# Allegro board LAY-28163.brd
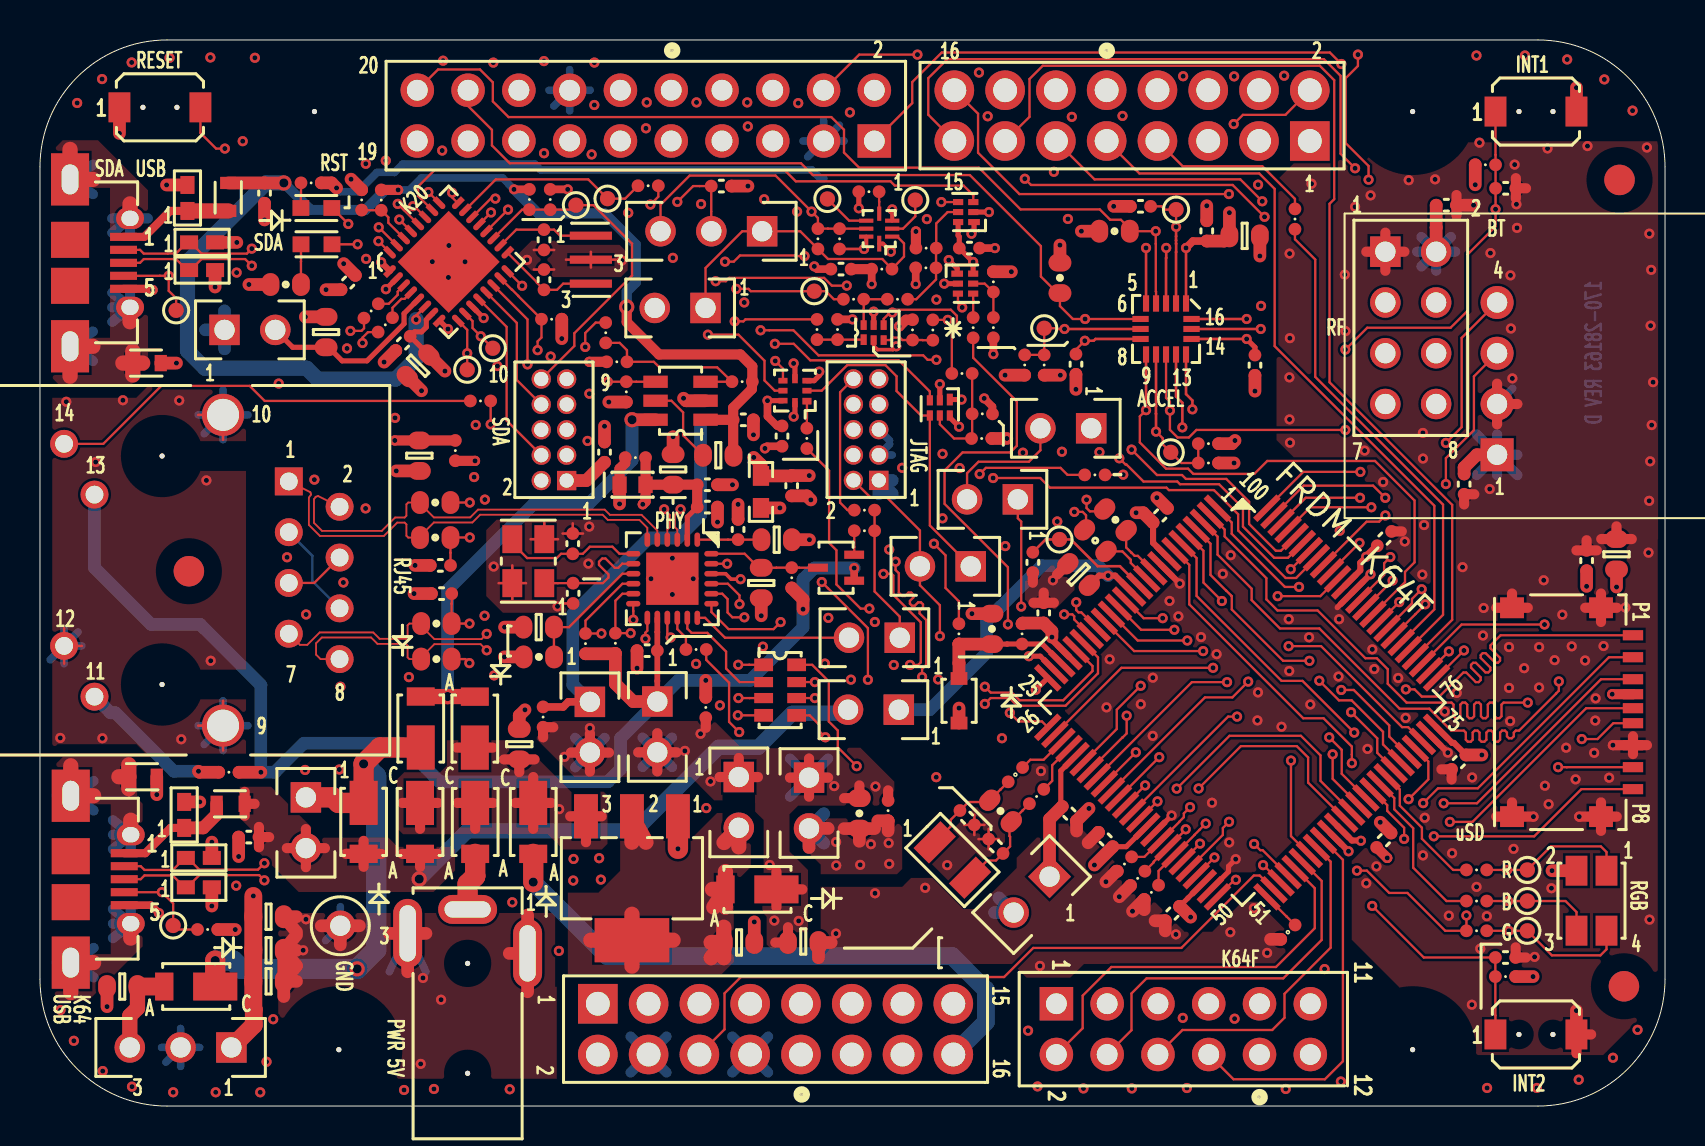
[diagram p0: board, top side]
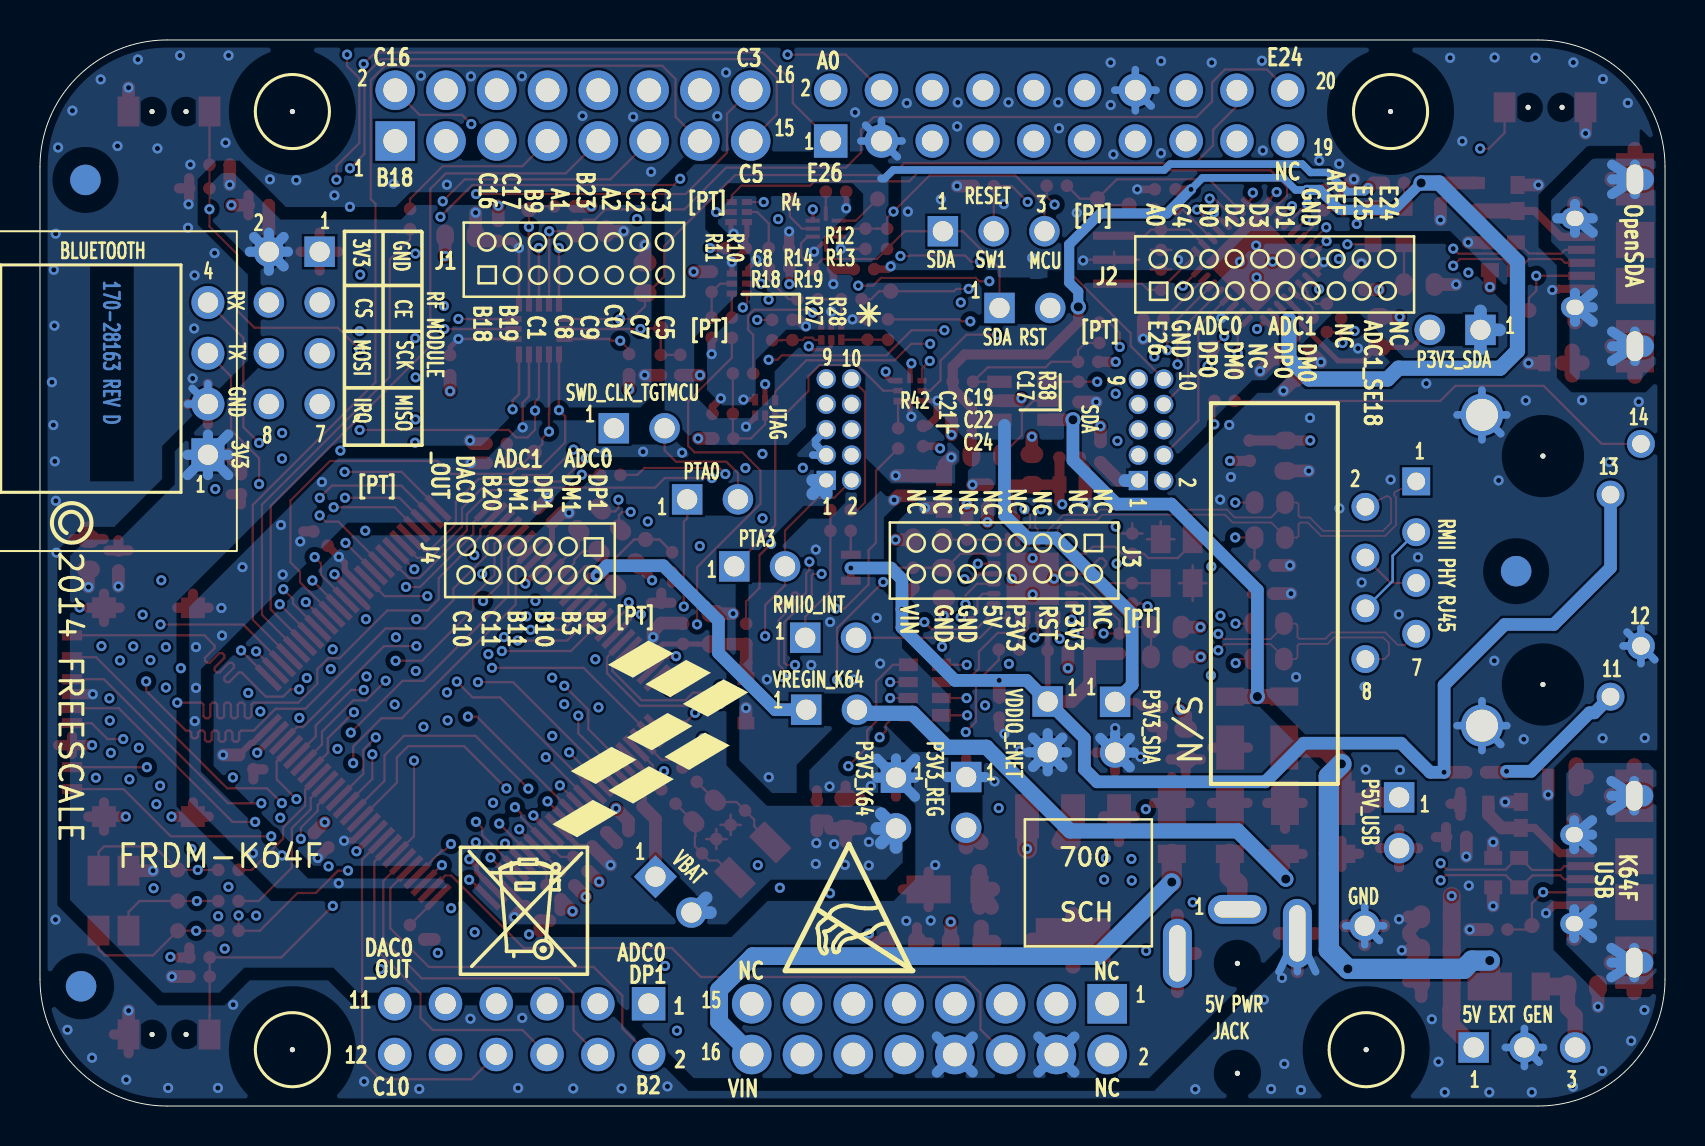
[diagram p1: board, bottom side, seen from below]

Outline 81.28 x 53.34 mm; copper layers: TOP, GND, INT_1, BOTTOM. Coordinates in mm from the lower left corner of the outline.
Outline path: 0,46.99 arc(1.86,51.48) 6.35,53.34 74.93,53.34 arc(79.42,51.48) 81.28,46.99 81.28,6.35 arc(79.42,1.86) 74.93,0 6.35,0 arc(1.86,1.86) 0,6.35 0,46.99

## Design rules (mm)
net group ADC0: nets ADC0_DM0/ADC1_DM3 ADC0_DP0/AD1_DP3
net group ADC1: nets ADC1_DM0/ADC0_DM3 ADC1_DP0/ADC0_DP3
net group ENET1_RX: nets ENET1_RX+ ENET1_RX-
net group ENET1_TX: nets ENET1_TX+ ENET1_TX-
net group LEDRGB_BLUE: nets LEDRGB_BLUE PTB21
net group LEDRGB_GREEN: nets LEDRGB_GREEN PTE26
net group LEDRGB_RED: nets LEDRGB_RED PTB22
net group PTB16: nets PTB16 UART1_RX_TGTMCU_BUF
net group PTB17: nets PTB17 UART1_TX_TGTMCU_BUF
net group RMII_RXCLK: nets RMII_RXCLK RXCLK
net group SDA_SWD_EN_B_R: nets SDA_SWD_EN_B SDA_SWD_EN_B_R
net group SDA_SWD_OE_B_R: nets SDA_SWD_OE_B SDA_SWD_OE_B_R
net group TRACE_SWO: nets PTA2 TRACE_SWO
net group USB_CONN_DN: nets K64_MICRO_USB_DN USB_CONN_DN
net group USB_CONN_DP: nets K64_MICRO_USB_DP USB_CONN_DP
net group USB_SI_CONN_D: nets SDA_USB_CONN_DN SDA_USB_CONN_DP
net group VTRG_EN: nets POWER_EN VTRG_EN
net group ANALOG: nets ADC0_DM1 ADC0_DP1 ADC1_DM1 ADC1_DP1 ADC1_SE18 DAC0_OUT PTB2 PTB3 PTB10 PTB11 PTC11
net group CLOCKS: nets PTB18 PTC3 PTC6 PTC8 PTD1 PTE0 RMII_XTALI RMII_XTALO SDA_EXTAL SWD_CLK_TGTMCU SWD_CLK_TGTMCU_BUF XTAL_K64_MAIN
net group CPU_PER_1_RST_B: nets CPU_PER_1_RST_B PHY_RST_B RST_TGTMCU_B SDA_RST_LED SDA_RST_TGTMCU_J_B V_TGTMCU
net group EXTAL32_RTC: nets EXTAL32_RTC EXTAL_32.768KHZ XTAL32_RTC XTAL_32.768KHZ
net group POW: nets VREFH
net group POWER_SPACE: nets P5-9V_VIN P5V0_SDA_USB_CONN_VBUS P5V0_USB_CONN_VBUS P5V_SDA P5V_USB SDA_VOUT33 VBAT VDDA_ENET VOUT33_K64 VREGIN_K64
net group SDA_SWD_EN_R: nets SDA_SPI0_RST_B SDA_SWD_EN SDA_SWD_EN_R
net group SDA_SWD_OE_R: nets SDA_SPI0_CS SDA_SWD_OE SDA_SWD_OE_R
net group SDA_USB_CONN_DP: nets SDA_USB_DP
net group USB_SI_D: nets SDA_USB_DN
nets with their own width: min track width 0.127; nets GND

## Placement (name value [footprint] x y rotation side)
C1  1.0UF  [CC0402_25]  11.23 45.68 270 top
C2  1000pF  [CC0402_25]  34.08 46.03 0 top
C3  0.1UF  [CC0402_25]  55.04 45.02 180 top
C4  0.1UF  [CC0402_25]  58.36 43.79 90 top
C5  4.7uF  [CC0603_OV]  60.25 43.54 0 top
C6  22PF  [CC0402_25]  25.21 43.34 270 top
C7  0.1UF  [CC0402_25]  46.49 42.93 0 top
C8  0.1UF  [CC0402_25]  40.07 41.87 180 top
C9  22PF  [CC0402_25]  25.21 41.35 90 top
C10  0.1UF  [CC0402_25]  15.42 41.2 225 top
C11  2.2UF  [CC0603_OV]  14.31 38.72 90 top
C12  1.0UF  [CC0402_25]  18.16 38.16 225 top
C13  0.1UF  [CC0402_25]  51.82 37.12 270 top
C14  0.1UF  [CC0402_25]  60.77 37.07 270 top
C15  10uF  [CC0603_OV]  18.91 37.04 225 top
C16  0.1UF  [CC0402_25]  35.18 34.33 0 top
C17  4.7uF  [CC0402_25]  37.11 33.52 270 top
C18  0.1UF  [CC0402_25]  28.24 32.72 90 top
C19  18PF  [CC0603_OV]  33.93 32.56 180 top
C20  10UF  [CC0603_OV]  18.97 32.54 270 top
C21  4.7UF  [CC0603_OV]  31.67 31.85 90 top
C22  0.1UF  [CC0402_25]  33.38 31.08 0 top
C23  4.7uF  [CC0402_25]  37.6 31.04 270 top
C24  0.1UF  [CC0402_25]  33.38 29.97 0 top
C25  0.1UF  [CC0402_25]  56.03 29.55 45 top
C26  0.1UF  [CC0402_25]  34.92 28.85 90 top
C27  0.1UF  [CC0402_25]  67.25 28.39 45 top
C28  1.0 UF  [CC0603_OV]  36.85 28.34 0 top
C29  24PF  [CC0402_25]  26.65 28.14 90 top
C30  10uF  [CC0603_OV]  78.85 27.61 90 top
C31  0.1UF  [CC0402_25]  20.03 27.05 180 top
C32  0.1UF  [CC0402_25]  77.36 27.29 90 top
C33  10uF  [CC0603_OV]  51.95 26.59 135 top
C34  10UF  [CC0603_OV]  36.08 26.17 270 top
C35  24PF  [CC0402_25]  26.66 25.65 270 top
C36  0.1UF  [CC0402_25]  20.09 25.64 180 top
C37  0.1UF  [CC0402_25]  50.2 24.67 90 top
C38  100PF  [CC0603_OV]  24.95 23.96 180 top
C39  0.1UF  [CC0402_25]  30.37 22.78 180 top
C40  2.2UF  [CC0603_OV]  38.18 8.18 0 top
C41  10uF  [CC0603_OV]  23.97 18.11 90 top
C42  0.1UF  [CC0402_25]  70.97 17.21 225 top
C43  0.1UF  [CC0402_25]  51.49 14.63 315 top
C44  12PF  [CC0402_25]  46.37 14.43 315 top
C45  1.0UF  [CC0402_25]  10.44 13.46 180 top
C46  0.1UF  [CC0402_25]  53.3 13.33 135 top
C47  0.1UF  [CC0402_25]  67.22 13.3 45 top
C48  12PF  [CC0402_25]  47.81 13 135 top
C49  0.1UF  [CC0402_25]  56.64 9.63 225 top
C50  10uF  [CC0603_OV]  11.43 9.47 0 top
C51  10uF  [CC0603_OV]  34.97 8.18 0 top
C52  10uF  [CC0603_OV]  11.43 7.79 0 top
C53  10uF  [CC0603_OV]  4.11 5.98 180 top
C54  10uF  [CC0603_OV]  11.43 6.24 0 top
C55  0.1UF  [CC0402_25]  73.3 7.43 0 top
C56  0.1UF  [CC0402_25]  73.31 45.92 0 top
C57  0.1UF  [CC0402_25]  70.34 45.07 0 top
C58  0.1UF  [CC0402_25]  71.23 31.12 270 top
C59  2.2uF  [CC0402_25]  49.66 27.2 270 top
D1  RED  [LED_0603]  13.82 44.93 0 top
D2  LED GREEN  [LED_0603]  13.83 43.12 0 top
D3  BAT54AWT1G  [SOT323_3P]  39.82 26.93 90 top
D4  3.0V  [SOD-323-A]  45.97 20.28 270 top
D5  DFLS130L-7  [POWERDI-123_3MMX2MM]  19.04 18.79 90 top
D6  DFLS130L-7  [POWERDI-123_3MMX2MM]  21.75 18.78 90 top
D7  DFLS130L-7  [POWERDI-123_3MMX2MM]  16.19 14.32 270 top
D8  DFLS130L-7  [POWERDI-123_3MMX2MM]  19.01 14.32 270 top
D9  DFLS130L-7  [POWERDI-123_3MMX2MM]  21.77 14.32 270 top
D10  DFLS130L-7  [POWERDI-123_3MMX2MM]  24.67 14.32 270 top
D11  DFLS130L-7  [POWERDI-123_3MMX2MM]  35.98 10.84 180 top
D12  CLV1A-FKB-CJ1M1F1BB7R4S3  [LED4_3P4X3MM_SMT]  77.6 10.27 0 top
D13  DFLS130L-7  [POWERDI-123_3MMX2MM]  7.91 5.98 180 top
J1  SSW-108-01-T-D  [CON_SKT2X8_TH]  63.51 48.29 0 top
J2  CON_2X10  [CON2X10_2P54_TH]  41.73 48.29 270 top
J3  SSW-108-01-T-D  [CON_SKT2X8_TH]  27.9 5.12 180 top
J4  SKT_2X6  [CON_SKT2X6_TH]  50.84 5.12 180 top
J5  HDR 1X2 TH  [SH_HDR102_BOTTOM]  33.29 39.93 270 top
J6  HDR_2X4  [HDR2X4]  67.29 42.75 0 top
J7  HDR 1X2 TH  [SH_HDR102_BOTTOM]  9.23 38.83 90 top
J8  HDR 1X2 TH  [SH_HDR102_BOTTOM]  52.58 33.91 270 top
J9  HDR 2X5  [HDR_5X2_FTSH_TH_NSP]  41.96 31.3 180 top
J10  HDR 2X5  [HDR_5X2_FTSH_TH_NSP]  26.34 31.3 180 top
J11  HDR 1X2 TH  [SH_HDR102_BOTTOM]  48.91 30.36 270 top
J12  HDR 1X2 TH  [SH_HDR102_BOTTOM]  46.55 27 270 top
J13  RB1-125BAG1A  [CON_RJ45_8P_2P54_TH_RA]  12.45 31.25 90 top
J14  HDR 1X2  [HDR102]  43 23.43 270 top
J15  CON microSD  [CON8_SDCARD_PUSH_SM]  75.75 19.71 90 top
J16  HDR 1X2 TH  [SH_HDR102_BOTTOM]  42.96 19.83 270 top
J17  HDR 1X2  [HDR102]  30.88 20.24 0 top
J18  HDR 1X2  [HDR102]  27.51 20.22 0 top
J19  HDR 1X2 TH  [SH_HDR102_BOTTOM]  34.95 16.46 0 top
J20  HDR 1X2  [HDR102]  38.47 16.43 0 top
J21  HDR 1X2  [HDR102]  13.3 15.44 0 top
J22  MICRO USB AB 5  [CON5_MICROUSB]  1.54 11.35 270 top
J23  HDR 1X2 TH  [SH_HDR102_BOTTOM]  50.5 11.48 315 top
J24  CON PWR 3  [CON_JACK_PJ1_022_TH-RA]  21.39 9.84 90 top
J25  HDR_1X3  [HDR103]  36.12 43.77 270 top
J26  MICRO USB AB 5  [CON5_MICROUSB]  1.5 42.19 270 top
J27  HDR_1X3  [HDR103]  9.57 2.93 270 top
J199  CON_1X4  [CON1X4_100_TH_RA]  72.88 32.59 90 bottom
L1  330 OHM  [IND_1608]  9.42 45.49 90 top
L2  330 OHM  [IND_1608]  5.34 37.17 0 top
L3  120OHM  [0603_CC]  29.64 31.09 0 top
L4  330 OHM  [IND_1608]  5.14 16.47 0 top
L5  330 OHM  [IND_1608]  9.54 15.12 0 top
NOREF  -  []  -381.97 185.27 0 top
NOREF#2  -  []  57.81 43.38 0 top
NOREF#3  -  []  42.18 43.28 90 top
NOREF#4  -  []  55.32 37.6 0 top
NOREF#5  -  []  6.11 21.09 90 top
NOREF#6  -  []  55.32 37.6 90 top
NOREF#7  -  [unnamed#2]  7.45 26.76 0 top
NOREF#8  -  []  70.32 0.01 90 top
NOREF#9  -  []  -239.61 -215.75 0 top
NOREF#10  -  []  24.14 10.61 0 top
NOREF#11  -  []  12.45 31.25 90 top
NOREF#12  -  []  55.05 39.38 90 top
NOREF#13  -  []  0 41.47 0 top
NOREF#14  -  []  12.45 31.25 90 top
NOREF#15  -  []  12.45 23.63 0 top
NOREF#16  -  []  1.21 23.02 90 top
NOREF#17  -  []  57.82 40.38 90 top
NOREF#18  -  []  13.74 2.72 0 top
NOREF#19  -  []  35.45 17.74 90 top
NOREF#20  -  []  55.32 37.6 0 top
NOREF#21  -  []  12.88 1.39 0 top
NOREF#22  -  []  12.45 31.25 0 top
NOREF#23  -  []  6.11 32.52 90 top
NOREF#24  -  []  55.32 37.6 0 top
NOREF#25  -  []  42.6 44.62 270 top
NOREF#26  -  []  2.73 30.59 90 top
NOREF#27  -  []  42.63 43.9 270 top
NOREF#28  -  []  79.64 51.25 0 top
NOREF#29  -  []  12.45 31.25 90 top
NOREF#30  -  []  192.91 64.47 0 top
NOREF#31  -  []  42.63 44.3 90 top
NOREF#32  -  []  -408 -339.88 0 top
NOREF#33  -  []  1.21 23.02 0 top
NOREF#34  -  []  65.9 33.73 0 top
NOREF#35  -  [unnamed#2]  79.23 5.99 0 top
NOREF#36  -  []  55.05 38.88 90 top
NOREF#37  -  []  54.82 40.38 0 top
NOREF#38  -  []  14.99 29.98 90 top
NOREF#39  -  []  -115.86 -175.27 0 top
NOREF#40  -  []  17.32 17.74 0 top
NOREF#41  -  []  65.9 33.73 90 top
NOREF#42  -  []  13.74 2.72 0 top
NOREF#43  -  []  55.05 38.38 0 top
NOREF#44  -  [unnamed#2]  79 46.34 0 top
NOREF#45  -  []  9.16 19.03 90 top
NOREF#46  -  []  -16.59 -36.7 0 top
NOREF#47  -  []  79.75 41.86 180 top
NOREF#48  -  [unnamed#2]  7.45 26.76 180 bottom
NOREF#49  -  [unnamed#2]  79.23 5.99 180 bottom
NOREF#50  -  []  120.45 -123.7 180 bottom
NOREF#51  -  []  54.61 5.51 180 bottom
NOREF#52  -  []  74.41 -23.78 0 bottom
NOREF#53  -  [unnamed#2]  68.66 2.82 180 bottom
NOREF#54  -  []  70.12 -27.59 180 bottom
NOREF#55  -  []  51.23 -43.91 270 bottom
NOREF#56  -  [unnamed#2]  13.73 49.76 180 bottom
NOREF#57  -  [unnamed#2]  14.95 2.82 180 bottom
NOREF#58  -  []  54.66 12.88 180 bottom
NOREF#59  -  []  20.69 32.09 270 bottom
NOREF#60  -  []  59.2 8.4 180 bottom
NOREF#61  -  [unnamed#2]  79.01 46.34 180 bottom
NOREF#62  -  [unnamed#2]  68.66 49.76 180 bottom
NOREF#63  -  []  55.65 13.45 180 bottom
NOREF#64  -  []  91.82 39.52 180 bottom
R1  10.0K  [RC0402_25]  72.3 47.09 0 top
R2  100  [RC0402_25]  13.56 46.19 180 top
R3  0  [RC0402_25]  30.42 46.05 180 top
R4  4.7K  [RC0402_25]  41.46 45.75 180 top
R5  4.7K  [RC0402_25]  24.48 45.36 270 top
R6  10.0K  [RC0402_25]  25.52 45.36 90 top
R7  10.0K  [RC0402_25]  16.09 45.34 90 top
R8  4.7K  [RC0402_25]  17.07 45.33 270 top
R9  4.7K  [RC0603_OV]  53.75 43.77 0 top
R10  0  [RC0402_25]  38.91 43.39 90 top
R11  180K  [RC0402_25]  39.99 43.39 90 top
R12  4.7K  [RC0402_25]  44.32 42.93 0 top
R13  10.0K  [RC0402_25]  44.31 41.94 180 top
R14  10.0K  [RC0402_25]  42.11 41.87 0 top
R15  4.7K  [RC0603_OV]  51.02 41.44 270 top
R16  10.0K  [RC0402_25]  47.69 41.24 90 top
R17  220  [RC0603_OV]  12.29 41.1 0 top
R18  0  [RC0402_25]  40.69 40.37 180 top
R19  0  [RC0402_25]  42.89 40.37 0 top
R20  33  [RC0402_25]  16.56 39.78 45 top
R21  10.0K  [RC0402_25]  25.59 39.37 180 top
R22  33  [RC0402_25]  17.27 39.09 45 top
R23  4.7K  [RC0402_25]  47.69 38.95 90 top
R24  0  [RC0402_25]  46.68 38.94 270 top
R25  0  [RC0402_25]  38.86 38.85 90 top
R26  10.0K  [RC0402_25]  39.89 38.85 270 top
R27  10.0K  [RC0402_25]  43.64 38.83 90 top
R28  0  [RC0402_25]  44.66 38.83 90 top
R29  1.0K  [RC0402_25]  28.3 38.69 270 top
R30  15K  [RC0402_25]  28.85 37.24 180 top
R31  10.0K  [RC0402_25]  49.25 37.08 270 top
R32  10.0K  [RC0402_25]  50.23 37.08 90 top
R33  0  [RC0402_25]  46.12 36.65 0 top
R34  10.0K  [RC0402_25]  35.12 36.24 180 top
R35  10.0K  [RC0402_25]  29.33 35.73 90 top
R36  100  [RC0402_25]  22.03 35.28 180 top
R37  4.7K  [RC0402_25]  47.13 34.63 180 top
R38  0  [RC0402_25]  38.36 33.41 270 top
R39  10.0K  [RC0402_25]  47.1 33.4 0 top
R40  10.0K  [RC0402_25]  58.44 33.14 180 top
R41  0  [RC0402_25]  20.77 32.79 90 top
R42  0  [RC0402_25]  29.78 32.44 0 top
R43  10.0K  [RC0402_25]  58.44 32.17 0 top
R44  49.9  [RC0603_OV]  19.77 30.2 0 top
R45  0  [RC0402_25]  41.24 29.81 0 top
R46  33  [RC0603_OV]  53.79 29.33 315 top
R47  0  [RC0402_25]  41.24 28.78 180 top
R48  49.9  [RC0603_OV]  19.77 28.44 0 top
R49  33  [RC0603_OV]  52.78 28.29 315 top
R50  10.0K  [RC0402_25]  37.6 26.43 90 top
R51  49.9  [RC0603_OV]  19.83 24.14 0 top
R52  1K  [RC0603_OV]  47.61 23.87 270 top
R53  0  [RC0402_25]  45.96 23.62 90 top
R54  0  [RC0402_25]  49.12 23.62 270 top
R55  1.5K  [RC0402_25]  28.78 23.15 90 top
R56  1.5K  [RC0402_25]  27.28 23.14 90 top
R57  33  [RC0402_25]  32.82 22.84 180 top
R58  6.49K  [RC0603_OV]  24.95 22.47 180 top
R59  49.9  [RC0603_OV]  19.83 22.36 0 top
R60  0  [RC0402_25]  33.3 19.94 90 top
R61  0  [RC0402_25]  25.16 19.46 90 top
R62  0  [RC0402_25]  48.79 16.58 225 top
R63  0  [RC0402_25]  49.85 15.49 225 top
R64  0  [RC0402_25]  42.42 14.78 270 top
R65  1.0M  [RC0603_OV]  48.04 14.76 135 top
R66  10  [RC0603_OV]  40.98 14.64 270 top
R67  10.0K  [RC0402_25]  54.24 12.11 225 top
R68  430  [RC0402_25]  71.85 11.81 0 top
R69  10.0K  [RC0402_25]  54.9 11.39 225 top
R70  10.0K  [RC0402_25]  55.59 10.69 225 top
R71  270  [RC0402_25]  71.85 10.26 180 top
R72  0  [RC0402_25]  8.39 8.83 0 top
R73  270  [RC0402_25]  71.85 8.77 180 top
R74  0  [RC0402_25]  62.42 8.7 225 top
R75  10.0K  [RC0402_25]  73.3 6.48 180 top
R76  100  [RC0402_25]  9.45 16.7 180 top
R79  33  [RC0402_25]  62.77 44.38 270 top
R80  0  [RC0402_25]  52.76 31.58 0 top
RN1  33  [RNET_38V_0603]  37.02 20.81 0 top
SH1  0  [SH0603]  36.06 30.73 270 top
SW1  SW2_STM151XX  [SW2_4X3MM_SM]  6 49.97 0 top
SW2  SW2_STM151XX  [SW2_4X3MM_SM]  74.83 49.76 0 top
SW3  SW2_STM151XX  [SW2_4X3MM_SM]  74.82 3.58 0 top
TP1  -  [TPAD_030]  28.39 45.4 0 top
TP2  -  [TPAD_030]  39.39 45.38 270 top
TP3  -  [TPAD_030]  43.78 45.33 270 top
TP4  -  [TPAD_030]  56.82 44.85 270 top
TP5  -  [TPAD_030]  26.81 45.07 0 top
TP6  -  [TPAD_030]  38.73 40.77 0 top
TP7  -  [TPAD_030]  6.81 39.81 0 top
TP8  -  [TPAD_030]  50.23 38.92 270 top
TP9  -  [TPAD_030]  22.65 37.91 0 top
TP10  -  [TPAD_030]  21.37 36.84 0 top
TP11  -  [TPAD_030]  56.56 32.71 270 top
TP12  -  [TPAD_030]  50.99 28.35 180 top
TP13  -  [TPAD_030]  74.39 11.81 270 top
TP14  -  [TPAD_030]  74.39 10.26 270 top
TP15  -  [TPAD_030]  6.66 9.03 0 top
TP16  TEST POINT WHITE  [TEST_LOOP]  15.02 9.02 0 top
TP17  -  [TPAD_030]  74.39 8.77 270 top
U1  0402ESDA-MLP  [0402_MLP]  7.38 45.44 90 top
U2  74LVCH1T45  [UDFN6_1X1P5MM]  46.3 44.73 180 top
U3  NTSX2102GU8H  [XQFN8_1P45X1P25MM]  41.98 43.9 90 top
U4  0402ESDA-MLP  [0402_MLP]  8.11 43.21 0 top
U5  PK20DX128VFM5  [QFN32_S142EP]  20.44 42.24 45 top
U6  0402ESDA-MLP  [0402_MLP]  8.11 41.83 0 top
U7  74LVCH1T45  [UDFN6_1X1P5MM]  46.29 41.15 0 top
U8  FXOS8700CQ  [QFN5X3_0P5_3X3]  56.32 38.88 270 top
U9  NLX2G14  [ULLGA6_1P45X1_0P5MM]  41.7 38.7 90 top
U10  74LVC2T45GM,125  [QFN8_1P6X1P6MM]  37.76 35.79 180 top
U11  MIC2005-0.8YM6  [SOT23-6_A]  32.04 35.29 180 top
U12  74LVCH1T45  [UDFN6_1X1P5MM]  45.01 34.93 270 top
U13  KSZ8081RNACA  [QFN24_4X4MM_SLUG]  31.63 26.38 180 top
U14  MK64FN1M0VLL12  [LQFP100_0P5_14X14]  60.13 20.19 315 top
U15  0402ESDA-MLP  [0402_MLP]  7.21 14.57 90 top
U16  0402ESDA-MLP  [0402_MLP]  7.95 12.41 0 top
U17  NCP1117ST33T3G  [SOT223]  29.61 11.4 180 top
U18  0402ESDA-MLP  [0402_MLP]  7.95 10.94 0 top
Y1  8.00MHZ  [XTAL3_3P35X1P45_SM]  27.55 42.35 90 top
Y2  25MHZ  [XTAL4_3P4X2P7]  24.42 27.26 90 top
Y3  32.768KHZ  [XTAL2-3P2X1P5-SM]  45.64 12.31 315 top

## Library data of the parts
C1 C12 C45 = CAP_NP: signal model: DEFAULT_CAPACITOR_1e+06pF_2_1
C2 C44 C48 C59 = CAP_NP
C3 C4 C13 C14 C32 C55-C58 = CAP_NP: signal model: DEFAULT_CAPACITOR_100000pF_2_1
C5 = CAP_NP: signal model: DEFAULT_CAPACITOR_4.7e+06pF_2_1
C6 C9 = CAP_NP: signal model: DEFAULT_CAPACITOR_22.000000pF_2_1
C7 C8 C10 C16 C18 C25 C27 C37 C42 C46 C47 C49 = CAP_NP: tolerance: 10%; signal model: DEFAULT_CAPACITOR_100000pF_2_1
C11 C40 = CAP_NP: signal model: DEFAULT_CAPACITOR_2.2e+06pF_2_1
C15 = CAP_NP: tolerance: 10%; signal model: DEFAULT_CAPACITOR_1e+07pF_2_1
C17 C23 = CAP_NP: tolerance: 10%; signal model: DEFAULT_CAPACITOR_4.7e+06pF_2_1
C19 = CAP_NP: tolerance: 5%; signal model: DEFAULT_CAPACITOR_18.000000pF_2_1
C20 C30 C34 C41 C50-C54 = CAP_NP: signal model: DEFAULT_CAPACITOR_1e+07pF_2_1
C21 = CAP_NP: signal model: DEFAULT_CAPACITOR_4.7e+06pF_2_1; room: RMII_PHY
C22 C24 C26 = CAP_NP: tolerance: 10%; signal model: DEFAULT_CAPACITOR_100000pF_2_1; room: RMII_PHY
C28 = CAP_NP: signal model: DEFAULT_CAPACITOR_1e+06pF_2_1; room: RMII_PHY
C29 C35 = CAP_NP: signal model: DEFAULT_CAPACITOR_24.000000pF_2_1
C31 C36 C39 = CAP_NP: signal model: DEFAULT_CAPACITOR_100000pF_2_1; room: RMII_PHY
C33 = CAP_NP: signal model: DEFAULT_CAPACITOR_1e+07pF_1_2
C38 = CAP_NP: signal model: DEFAULT_CAPACITOR_100.000000pF_2_1
C43 = CAP_NP: tolerance: 10%; signal model: DEFAULT_CAPACITOR_100000pF_1_2
D1 D2 = LED
D3 = DUALDIODE_CA_SOT23
D4 = ZDIODE
D5-D11 D13 = DIODE_SCHTKY
D12 = CLV1A_LED_4P
J1 J3 = HDR_2X8_M
J2 = CONN_HDR_10X2
J4 = CONN_HDR_6X2
J5 J7 J8 J11 J12 J14 J16-J21 J23 = CONN_HDR_2X1
J6 = CONN_HDR_4X2
J9 J10 = CONN_HDR_5X2
J13 = RJ45_RB1_125BAG1A
J15 = CON8_SDCARD_SW
J22 J26 = USB_MINI_AB_RECEPTACLE
J24 = DC POWER JACK
J25 J27 = CONN_HDR_3X1
J199 = CONN_HDR_4X1
L1 L2 L4 L5 = BEAD
L3 = BEAD_0: room: RMII_PHY
R1 R34 R35 R75 = RES: tolerance: 1%; signal model: DEFAULT_RESISTOR_10000OHM_2_1
R2 = RES: tolerance: 1%; signal model: DEFAULT_RESISTOR_100.000000OHM_2_1
R3 R18 R19 R25 R28 R33 R42 R45 R47 R53 R54 R60-R64 R72 R80 = RES: signal model: DEFAULT_RESISTOR_0.001OHM_2_1
R4 R5 R8 R12 R23 R37 = RES: tolerance: 1%; signal model: DEFAULT_RESISTOR_4700OHM_2_1
R6 R7 R21 R31 R32 R40 R43 = RES: signal model: DEFAULT_RESISTOR_10000OHM_2_1
R9 R15 = RES: signal model: DEFAULT_RESISTOR_4700OHM_2_1
R10 R24 R38 = RES: tolerance: 5%; signal model: DEFAULT_RESISTOR_0.001OHM_2_1
R11 = RES: signal model: DEFAULT_RESISTOR_180000OHM_2_1
R13 R14 R16 R26 R27 R39 = RES: tolerance: 5%; signal model: DEFAULT_RESISTOR_10000OHM_2_1
R17 = RES: signal model: DEFAULT_RESISTOR_220.000000OHM_2_1
R20 R22 R46 R49 R57 = RES: signal model: DEFAULT_RESISTOR_33.000000OHM_2_1
R29 = RES: tolerance: 1%; signal model: DEFAULT_RESISTOR_1000.000000OHM_2_1
R30 = RES: tolerance: 1%; signal model: DEFAULT_RESISTOR_15000OHM_2_1
R36 R76 R79 = RES
R41 = RES: tolerance: 5%; signal model: DEFAULT_RESISTOR_0.001OHM_2_1; room: RMII_PHY
R44 R48 R51 R59 = RES: tolerance: 1%; signal model: DEFAULT_RESISTOR_49.900000OHM_2_1; room: RMII_PHY
R50 R67 R69 R70 = RES: signal model: DEFAULT_RESISTOR_10000OHM_2_1; room: RMII_PHY
R52 = RES: signal model: DEFAULT_RESISTOR_1000.000000OHM_2_1
R55 R56 = RES: signal model: DEFAULT_RESISTOR_1500OHM_2_1; room: RMII_PHY
R58 = RES: signal model: DEFAULT_RESISTOR_6490OHM_2_1
R65 = RES: signal model: DEFAULT_RESISTOR_1OHM_1_2
R66 = RES: signal model: DEFAULT_RESISTOR_10.000000OHM_2_1
R68 = RES: signal model: DEFAULT_RESISTOR_680.000000OHM_2_1
R71 R73 = RES: signal model: DEFAULT_RESISTOR_330.000000OHM_2_1
R74 = RES: tolerance: 1%; signal model: DEFAULT_RESISTOR_0.001OHM_1_2
RN1 = Resistor_Array
SH1 = RES_SHORT-2: signal model: DEFAULT_RESISTOR_0.001OHM_2_1
SW1-SW3 = SW2_STM151XX
TP1-TP15 TP17 = TESTLOOP
TP16 = TestLoop
U1 U4 U6 U15 U16 U18 = DIODE_TVS_BIDIR
U2 U7 U12 = 74LVCH1T45_6P
U3 = NTSX2102GU8H_8P
U5 = PK20DX128V_QFN_32P
U8 = FXOS8700CQ_QFN_16P
U9 = NLU2GU04
U10 = 74LVC2T45GM_8P
U11 = MIC2005-0.8YM6
U13 = KSZ8081RNACA_QFN_24P
U14 = K64FN1M0VLL12_100P
U17 = LD1117AS18
Y1 = XTAL_CS
Y2 = CRYSTAL13
Y3 = XTAL

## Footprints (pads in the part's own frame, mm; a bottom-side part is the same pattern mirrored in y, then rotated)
0402_MLP
  rect 0.9x0.7 smd: 1(-0.65,0) 2(0.65,0)
0603_CC
  rect 0.711x0.838 smd: 1(-0.65,0) 2(0.65,0)
CC0402_25
  round 0.635 smd: 1(-0.508,0) 2(0.508,0)
CC0603_OV
  oval 0.889x1.143 smd: 1(-0.762,0) 2(0.762,0)
CON1X4_100_TH_RA
  rect 1.651x1.651 hole 1.016: 1(0,0)
  round 1.651 hole 1.016: 2(2.54,0) 3(5.08,0) 4(7.62,0)
CON2X10_2P54_TH
  rect 1.676x1.676 hole 1.041: 1(0,0)
  round 1.676 hole 1.041: 2(-2.54,0) 3(0,-2.54) 4(-2.54,-2.54) 5(0,-5.08) 6(-2.54,-5.08) 7(0,-7.62) 8(-2.54,-7.62) 9(0,-10.16) 10(-2.54,-10.16) 11(0,-12.7) 12(-2.54,-12.7) 13(0,-15.24) 14(-2.54,-15.24) 15(0,-17.78) 16(-2.54,-17.78) 17(0,-20.32) 18(-2.54,-20.32) 19(0,-22.86) 20(-2.54,-22.86)
CON5_MICROUSB
  rect 1.803x1.905 smd: (-1.15,0) (1.15,0)
  rect 0.406x1.346 smd: 1(-1.3,2.675) 2(-0.65,2.675) 3(0,2.675) 4(0.65,2.675) 5(1.3,2.675)
  oval 1.067x1.397 hole 0.762x0.864: S1(-2.225,3) S2(2.225,3)
  rect 2.616x1.905 hole 1.499x0.838: S3(-4.175,0) S4(4.175,0)
CON8_SDCARD_PUSH_SM
  rect 0.508x1.016 smd: G1(0.2,-3.925) P1(3.85,-3.925) P2(2.75,-3.925) P3(1.65,-3.925) P4(0.9,-3.925) P5(-0.55,-3.925) P6(-1.65,-3.925) P7(-2.75,-3.925) P8(-3.85,-3.925)
  rect 1.041x1.194 smd: S1(5.225,-2.325) S2(5.225,2.125) S3(-5.225,2.125) S4(-5.225,-2.325)
CON_JACK_PJ1_022_TH-RA
  round 0.254 hole 1.6 unplated: (-8.2,0) (-2.7,0)
  oval 1.448x2.946 hole 0.813x2.311: 1(0,0)
  oval 3.454x1.448 hole 2.819x0.813: 2(-2.2,-3) 3(-1.2,3)
CON_RJ45_8P_2P54_TH_RA
  round 0.254 hole 3.251 unplated: (-10.16,6.34) (1.27,6.34)
  rect 1.397x1.397 hole 0.889: 1(0,0)
  round 1.397 hole 0.889: 2(-1.27,-2.54) 3(-2.54,0) 4(-3.81,-2.54) 5(-5.08,0) 6(-6.35,-2.54) 7(-7.62,0) 8(-8.89,-2.54) 11(-10.77,9.72) 12(-8.23,11.24) 13(-0.66,9.72) 14(1.88,11.24)
  round 2.108 hole 1.6: 9(-12.22,3.29) 10(3.33,3.29)
CON_SKT2X6_TH
  rect 1.676x1.676 hole 1.041: 1(0,0)
  round 1.676 hole 1.041: 2(0,2.54) 3(-2.54,0) 4(-2.54,2.54) 5(-5.08,0) 6(-5.08,2.54) 7(-7.62,0) 8(-7.62,2.54) 9(-10.16,0) 10(-10.16,2.54) 11(-12.7,0) 12(-12.7,2.54)
CON_SKT2X8_TH
  rect 1.981x1.981 hole 1.194: 1(0,0)
  round 1.981 hole 1.194: 2(0,2.54) 3(-2.54,0) 4(-2.54,2.54) 5(-5.08,0) 6(-5.08,2.54) 7(-7.62,0) 8(-7.62,2.54) 9(-10.16,0) 10(-10.16,2.54) 11(-12.7,0) 12(-12.7,2.54) 13(-15.24,0) 14(-15.24,2.54) 15(-17.78,0) 16(-17.78,2.54)
HDR2X4
  rect 1.524x1.524 hole 1.016: 1(0,0)
  round 1.524 hole 1.016: 2(2.54,0) 3(0,-2.54) 4(2.54,-2.54) 5(0,-5.08) 6(2.54,-5.08) 7(0,-7.62) 8(2.54,-7.62)
HDR102
  rect 1.524x1.524 hole 1.016: 1(0,0)
  round 1.524 hole 1.016: 2(0,-2.54)
HDR103
  rect 1.524x1.524 hole 1.016: 1(0,0)
  round 1.524 hole 1.016: 2(0,-2.54) 3(0,-5.08)
HDR_5X2_FTSH_TH_NSP
  rect 0.965x0.965 hole 0.711: 1(0,0)
  round 0.965 hole 0.711: 2(1.27,0) 3(0,-1.27) 4(1.27,-1.27) 5(0,-2.54) 6(1.27,-2.54) 7(0,-3.81) 8(1.27,-3.81) 9(0,-5.08) 10(1.27,-5.08)
IND_1608
  rect 0.61x0.813 smd: 1(-0.7,0) 2(0.7,0)
LED4_3P4X3MM_SMT
  rect 1.092x1.499 smd: 1(0.75,1.5) 2(-0.75,1.5) 3(-0.75,-1.5) 4(0.75,-1.5)
LED_0603
  rect 0.838x0.787 smd: A(-0.775,0) C(0.775,0)
LQFP100_0P5_14X14
  rect 1.651x0.305 smd: 1(-7.75,6) 2(-7.75,5.5) 3(-7.75,5) 4(-7.75,4.5) 5(-7.75,4) 6(-7.75,3.5) 7(-7.75,3) 8(-7.75,2.5) 9(-7.75,2) 10(-7.75,1.5) 11(-7.75,1) 12(-7.75,0.5) 13(-7.75,0) 14(-7.75,-0.5) 15(-7.75,-1) 16(-7.75,-1.5) 17(-7.75,-2) 18(-7.75,-2.5) 19(-7.75,-3) 20(-7.75,-3.5) 21(-7.75,-4) 22(-7.75,-4.5) 23(-7.75,-5) 24(-7.75,-5.5) 25(-7.75,-6) 51(7.75,-6) 52(7.75,-5.5) 53(7.75,-5) 54(7.75,-4.5) 55(7.75,-4) 56(7.75,-3.5) 57(7.75,-3) 58(7.75,-2.5) 59(7.75,-2) 60(7.75,-1.5) 61(7.75,-1) 62(7.75,-0.5) 63(7.75,0) 64(7.75,0.5) 65(7.75,1) 66(7.75,1.5) 67(7.75,2) 68(7.75,2.5) 69(7.75,3) 70(7.75,3.5) 71(7.75,4) 72(7.75,4.5) 73(7.75,5) 74(7.75,5.5) 75(7.75,6)
  rect 0.305x1.651 smd: 26(-6,-7.75) 27(-5.5,-7.75) 28(-5,-7.75) 29(-4.5,-7.75) 30(-4,-7.75) 31(-3.5,-7.75) 32(-3,-7.75) 33(-2.5,-7.75) 34(-2,-7.75) 35(-1.5,-7.75) 36(-1,-7.75) 37(-0.5,-7.75) 38(0,-7.75) 39(0.5,-7.75) 40(1,-7.75) 41(1.5,-7.75) 42(2,-7.75) 43(2.5,-7.75) 44(3,-7.75) 45(3.5,-7.75) 46(4,-7.75) 47(4.5,-7.75) 48(5,-7.75) 49(5.5,-7.75) 50(6,-7.75) 76(6,7.75) 77(5.5,7.75) 78(5,7.75) 79(4.5,7.75) 80(4,7.75) 81(3.5,7.75) 82(3,7.75) 83(2.5,7.75) 84(2,7.75) 85(1.5,7.75) 86(1,7.75) 87(0.5,7.75) 88(0,7.75) 89(-0.5,7.75) 90(-1,7.75) 91(-1.5,7.75) 92(-2,7.75) 93(-2.5,7.75) 94(-3,7.75) 95(-3.5,7.75) 96(-4,7.75) 97(-4.5,7.75) 98(-5,7.75) 99(-5.5,7.75) 100(-6,7.75)
POWERDI-123_3MMX2MM
  rect 0.914x1.397 smd: A(1.7,0)
  rect 2.21x1.397 smd: C(-0.85,0)
QFN5X3_0P5_3X3
  rect 0.813x0.305 smd: 1(-1.275,1) 2(-1.275,0.5) 3(-1.275,0) 4(-1.275,-0.5) 5(-1.275,-1) 9(1.275,-1) 10(1.275,-0.5) 11(1.275,0) 12(1.275,0.5) 13(1.275,1)
  rect 0.305x0.813 smd: 6(-0.5,-1.275) 7(0,-1.275) 8(0.5,-1.275) 14(0.5,1.275) 15(0,1.275) 16(-0.5,1.275)
QFN8_1P6X1P6MM
  rect 0.457x0.33 smd: 1(-0.6,0.525)
  rect 0.457x0.279 smd: 2(-0.6,0) 3(-0.6,-0.5) 5(0.6,-0.5) 6(0.6,0) 7(0.6,0.5)
  rect 0.279x0.457 smd: 4(0,-0.6) 8(0,0.6)
QFN24_4X4MM_SLUG
  oval 0.279x0.711 smd: 1(-1.25,-1.956) 2(-0.75,-1.956) 3(-0.25,-1.956) 4(0.25,-1.956) 5(0.75,-1.956) 6(1.25,-1.956) 13(1.25,1.956) 14(0.75,1.956) 15(0.25,1.956) 16(-0.25,1.956) 17(-0.75,1.956) 18(-1.25,1.956)
  oval 0.711x0.279 smd: 7(1.956,-1.25) 8(1.956,-0.75) 9(1.956,-0.25) 10(1.956,0.25) 11(1.956,0.75) 12(1.956,1.25) 19(-1.956,1.25) 20(-1.956,0.75) 21(-1.956,0.25) 22(-1.956,-0.25) 23(-1.956,-0.75) 24(-1.956,-1.25)
  rect 2.616x2.616 smd: 25(0,0)
QFN32_S142EP
  custom 0.07x0.07 smd: 1(-2.4,1.751) 2(-2.4,1.251) 3(-2.4,0.751) 4(-2.4,0.25) 5(-2.4,-0.25) 6(-2.4,-0.751) 7(-2.4,-1.251) 8(-2.4,-1.751) 9(-1.751,-2.4) 10(-1.251,-2.4) 11(-0.751,-2.4) 12(-0.25,-2.4) 13(0.25,-2.4) 14(0.751,-2.4) 15(1.251,-2.4) 16(1.751,-2.4) 17(2.4,-1.751) 18(2.4,-1.251) 19(2.4,-0.751) 20(2.4,-0.25) 21(2.4,0.25) 22(2.4,0.751) 23(2.4,1.251) 24(2.4,1.751) 25(1.751,2.4) 26(1.251,2.4) 27(0.751,2.4) 28(0.25,2.4) 29(-0.25,2.4) 30(-0.751,2.4) 31(-1.251,2.4) 32(-1.751,2.4)
  rect 3.607x3.607 smd: 33(0,0)
RC0402_25
  round 0.635 smd: 1(-0.508,0) 2(0.508,0)
RC0603_OV
  oval 0.889x1.143 smd: 1(-0.762,0) 2(0.762,0)
RNET_38V_0603
  rect 0.94x0.635 smd: 1(-0.825,1.263) 4(-0.825,-1.263) 5(0.825,-1.263) 8(0.825,1.263)
  rect 0.94x0.508 smd: 2(-0.825,0.4) 3(-0.825,-0.4) 6(0.825,-0.4) 7(0.825,0.4)
SH0603
  rect 0.991x0.813 smd: 1(-0.8,0) 2(0.8,0)
SH_HDR102_BOTTOM
  rect 1.524x1.524 hole 1.016: 1(0,0)
  round 1.524 hole 1.016: 2(0,-2.54)
SOD-323-A
  rect 0.635x0.838 smd: A(1.115,0) C(-1.115,0)
SOT23-6_A
  rect 1.219x0.61 smd: 1(-1.25,0.95) 2(-1.25,0) 3(-1.25,-0.95) 4(1.25,-0.95) 5(1.25,0) 6(1.25,0.95)
SOT223
  rect 1.194x2.21 smd: 1(-2.3,-3.1) 2(0,-3.1) 3(2.3,-3.1)
  rect 3.734x2.21 smd: 4(0,3.1)
SOT323_3P
  rect 0.406x0.991 smd: 1(-0.65,-0.907) 2(0.65,-0.907) 3(0,0.907)
SW2_4X3MM_SM
  round 0.254 hole 0.711 unplated: (-0.85,0) (0.85,0)
  rect 1.092x1.499 smd: 1(-2.025,0) 2(2.025,0)
TEST_LOOP
  round 1.524 hole 1.016: 1(0,0)
TPAD_030
  round 0.762 smd: 1(0,0)
UDFN6_1X1P5MM
  rect 0.584x0.305 smd: 1(-0.418,0.5)
  rect 0.508x0.305 smd: 2(-0.38,0) 3(-0.38,-0.5) 4(0.38,-0.5) 5(0.38,0) 6(0.38,0.5)
ULLGA6_1P45X1_0P5MM
  rect 0.533x0.305 smd: 1(-0.355,0.5)
  rect 0.483x0.305 smd: 2(-0.375,0) 3(-0.375,-0.5) 4(0.375,-0.5) 5(0.375,0) 6(0.375,0.5)
unnamed#2
  round 1.524 smd: (0,0)
XQFN8_1P45X1P25MM
  rect 0.787x0.203 smd: 1(-0.75,0)
  rect 0.203x0.711 smd: 2(-0.4,-0.65) 3(0,-0.65) 4(0.4,-0.65) 6(0.4,0.65) 7(0,0.65) 8(-0.4,0.65)
  rect 0.711x0.203 smd: 5(0.75,0)
XTAL2-3P2X1P5-SM
  rect 1.092x1.905 smd: 1(-1.25,0) 2(1.25,0)
XTAL3_3P35X1P45_SM
  rect 0.406x2.108 smd: 1(1.2,0) 2(0,0) 3(-1.2,0)
XTAL4_3P4X2P7
  rect 1.397x0.991 smd: 1(-1.1,-0.8) 2(1.1,-0.8) 3(1.1,0.8) 4(-1.1,0.8)

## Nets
GND: C1.2 C2.2 C3.2 C4.2 C5.2 C6.2 C7.2 C8.2 C9.2 C10.2 C11.2 C12.2 C13.2 C14.2 C15.2 C16.2 C17.2 C18.2 C20.2 C21.2 C22.2 C23.2 C24.2 C25.2 C26.2 C27.2 C28.2 C29.2 C30.2 C31.2 C32.2 C33.2 C34.2 C35.2 C36.2 C37.2 C38.2 C39.2 C40.2 C41.2 C42.2 C43.2 C44.2 C45.2 C46.2 C47.2 C48.2 C49.2 C50.2 C51.2 C52.2 C53.2 C54.2 C55.2 C56.2 C57.2 C58.2 C59.2 D4.A(ANODE) J2.3 J2.14 J3.12 J3.14 J6.1(A1) J9.3(A2) J9.5(A3) J10.3(A2) J10.5(A3) J13.9(SH1) J13.10(SH2) J13.12(L2) J15.P6(VSS) J15.S1 J15.S2 J15.S3 J15.S4 J22.5(P5) J24.2 J24.3 J26.5(P5) J27.2 J199.2 L2.2 L4.2 R6.2 R7.2 R13.2 R16.2 R30.2 R31.2 R39.2 R43.2 R58.2 R67.2 R69.2 R70.2 R72.2 R74.2 SW1.1(SW1) SW2.2(SW2) SW3.2(SW2) TP16.1(PIN1) U1.2(A2) U2.2(GND) U3.4(GND) U4.2(A2) U5.2(VSS1) U5.8(VSSA) U5.33(EPAD) U6.2(A2) U7.2(GND) U8.3(RSVD1) U8.5(GND1) U8.12(GND2) U8.13(RSVD2) U8.16(RST) U9.2(GND) U10.3(DIR) U10.4(GND) U11.2(GND) U12.2(GND) U13.22(GND1) U13.25(GND2) U14.9(VSS1) U14.24(VREFL) U14.25(VSSA) U14.41(VSS2) U14.49(VSS3) U14.60(VSS4) U14.74(VSS5) U14.88(VSS6) U15.2(A2) U16.2(A2) U17.1(GND) U18.2(A2) Y1.2 Y2.2 Y2.4
P3V3: C4.1 C5.1 C14.1 C30.1 C32.1 C40.1 C57.1 C58.1 D11.C D12.2(COMMON_A) J3.4 J3.8 J6.2(B1) J15.P4(VDD) J17.2 J18.2 J19.1 J20.1 J199.1 L3.1 R1.1 R9.1 R15.1 R32.1 R40.1 R42.1 R60.1 R61.1 R64.1 R66.1 R75.1 SH1.2 U8.1(VDDIO) U8.14(VDD)
P3V3_K64F: C25.1 C27.1 C37.1 C42.1 C46.1 C47.1 C49.1 J9.1(A1) J20.2 J23.2 R52.1 R54.1 R64.2 R66.2 U14.8(VDD1) U14.22(VDDA) U14.40(VDD2) U14.48(VDD3) U14.61(VDD4) U14.75(VDD5) U14.89(VDD6)
P3V3_SDA: C8.1 C10.1 C12.1 C15.1 C17.1 C18.1 J7.1 J10.1(A1) J18.1 R4.2 R12.1 R14.1 R17.1 R21.1 R23.1 R26.1 R27.2 R35.1 R37.1 R61.2 U2.1(VCCA) U3.1(VCCA) U5.1(VDD1) U5.7(VDDA) U5.11(VBAT) U7.1(VCCA) U9.5(VCC) U10.7(VCCA) U12.1(VCCA)
P3V3_VREG: C51.1 D11.A J19.2 U17.2(VOUT) U17.4(TAB)
P5V0_SDA_USB_CONN_VBUS: J26.1(P1) L1.1 U1.1(A1)
P5V0_USB_CONN_VBUS: J22.1(P1) L5.1 U15.1(A1)
P5V_K64_USB: C45.1 D7.A D8.A J16.2 J21.2 L5.2
P5V_OPT_VR: C53.1 D13.A J27.3
P5V_SDA: C1.1 C16.1 C19.1 L1.2 R5.1 R8.1 R34.1 U5.6(VREGIN) U11.1(VIN)
P5V_SDA_PSW: D5.A D6.A U11.6(VOUT)
P5V_USB: D5.C D7.C D13.C J3.10 J21.1
VBAT: C43.1 J23.1 U14.30(VBAT)
VDDA_ENET: C21.1 C22.1 C24.1 L3.2 R41.1 R42.2 U13.2(VDDA_3V3)
VDDIO_ENET: C39.1 D3.1(CATHODE1) J13.13(L3) J17.1 R50.1 R55.1 R56.1 R60.2 R76.1 U13.14(VDDIO)
VDDPLL_1.2V: C26.1 C28.1 U13.1(VDD_1V2)
ADC0_DM0/ADC1_DM3: J2.7 U14.19(ADC0_DM0/ADC1_DM3)
ADC0_DM1: J4.3(A2) U14.15(ADC0_DM1)
ADC0_DP0/AD1_DP3: J2.5 U14.18(ADC0_DP0/ADC1_DP3)
ADC0_DP1: J4.1(A1) U14.14(ADC0_DP1)
ADC1_DM0/ADC0_DM3: J2.13 U14.21(ADC1_DM0/ADC0_DM3)
ADC1_DM1: J4.7(A4) U14.17(ADC1_DM1)
ADC1_DP0/ADC0_DP3: J2.11 U14.20(ADC1_DP0/ADC0_DP3)
ADC1_DP1: J4.5(A3) U14.16(ADC1_DP1)
ADC1_SE18: J2.17 U14.26(VREF_OUT/CMP1_IN5/CMP0_IN5/ADC1)
AREF: J2.16 R53.2
CPU_PER_1_RST_B: J14.1 R45.2 R47.1
CRS_DV: RN1.1(PIN1) U13.15(CRS_RV/PHYAD1/PHYAD0)
DAC0_OUT: J4.11(A6) U14.27(DAC0_OUT/CMP1_IN3/ADC0_SE23)
DC_JACK: D9.A J24.1(PIN)
ENET1_CT: C20.1 J13.3(TCT) J13.6(RCT) R41.2
ENET1_RX+: J13.7(RD+) R51.1 U13.4(RXP)
ENET1_RX-: J13.8(RD-) R59.1 U13.3(RXM)
ENET1_TX+: J13.1(TD+) R48.1 U13.6(TXP)
ENET1_TX-: J13.2(TD-) R44.1 U13.5(TXM)
ENET_1_RX_RDIV: C36.1 R51.2 R59.2
ENET_1_TX_RDIV: C31.1 R44.2 R48.2
EXTAL32_RTC: R63.1 U14.29(EXTAL32)
EXTAL_32.768KHZ: C48.1 R63.2 R65.1 Y3.2
FXOS8700CQ_CRST: C13.1 U8.8(CRST)
FXOS8700CQ_I2C_SA0: R31.1 R32.2 TP8.1(PIN1) U8.7(SA0/MISO)
FXOS8700CQ_I2C_SA1: R40.2 R43.1 TP11.1(PIN1) U8.10(SA1/C\S\)
I2S_MCLK: J1.7 R79.1
K64_MICRO_USB_DN: R49.2 U14.11(USB0_DM)
K64_MICRO_USB_DP: R46.2 U14.10(USB0_DP)
LED1/SPEED: R36.1 U13.23(LED0/ANEN_SPEED)
LED2_LINK: J13.11(L1) R76.2
LEDRGB_BLUE: D12.3(BLUE_C) R71.1 TP14.1(PIN1)
LEDRGB_GREEN: D12.4(GREEN_C) R73.1 TP17.1(PIN1)
LEDRGB_RED: D12.1(RED_C) R68.2 TP13.1(PIN1)
LVLRST_EN: R4.1 U3.5(OE)
MIC2005_CSLEW: C19.2 U11.5(CSLEW)
MMA8451_BYP: C3.1 TP4.1(PIN1) U8.2(BYP)
NC1: J13.4(NC1#4) J13.5(NC1#5)
P5-9V_VIN: C50.1 C52.1 C54.1 D10.A J3.16 J27.1
P5-9V_VIN_VR: C41.1 D6.C D8.C D9.C D10.C U17.3(VIN)
PHY_RST_B: D3.2(CATHODE2) R47.2
POWER_EN: R29.1 U5.31(ADC0_SE7B/PTD6/SPI0_PCS3/UART0_)
PTA0: J2.2 J11.1 U14.34(PTA0/JTAG_TCLK/SWD_CLK/EZP_CLK/)
PTA1: J1.8 U14.35(PTA1/JTAG_TDI/EZP_DI/UART0_RX/F)
PTA2: J1.12 R80.2 U14.36(PTA2/JTAG_TDO/TRACE_SWO/EZP_DO/)
PTA3: J9.2(B1) J12.2 U14.37(PTA3/JTAG_TMS/SWD_DIO/U\A\R\T\0)
PTA4: C55.1 R75.2 SW3.1(SW1) U14.38(PTA4/LLWU_P3/N\M\I\/E\Z\P\_\C\S)
PTA5: RN1.7(PIN7) U14.39(PTA5/USB_CLKIN/FTM0_CH2/RMII0_R)
PTA12: R67.1 RN1.6(PIN6) U14.42(PTA12/CMP2_IN0/CAN0_TX/FTM1_CH0)
PTA13: R69.1 RN1.5(PIN5) U14.43(PTA13/LLWU_P4/CMP2_IN1/CAN0_RX/)
PTA14: R70.1 RN1.8(PIN8) U14.44(PTA14/SPI0_PCS0/UART0_TX/RMII0_)
PTA15: U13.19(TXEN) U14.45(PTA15/SPI0_SCK/UART0_RX/RMII0_T)
PTA16: U13.20(TXD0) U14.46(PTA16/SPI0_SOUT/U\A\R\T\0\_\C\T)
PTA17: U13.21(TXD1) U14.47(PTA17/ADC1_SE17/SPI0_SIN/U\A\R\)
PTB0: R56.2 U13.10(MDIO) U14.53(PTB0/LLWU_P5/ADC0_SE8/ADC1_SE8/)
PTB1: R55.2 U13.11(MDC) U14.54(PTB1/ADC0_SE9/ADC1_SE9/I2C0_SDA)
PTB2: J4.2(B1) U14.55(PTB2/ADC0_SE12/I2C0_SCL/U\A\R\T)
PTB3: J4.4(B2) U14.56(PTB3/ADC0_SE13/I2C0_SDA/U\A\R\T)
PTB9: J1.6 U14.57(PTB9/SPI1_PCS1/U\A\R\T\3\_\C\T\)
PTB10: J4.6(B3) U14.58(PTB10/ADC1_SE14/SPI1_PCS0/UART3)
PTB11: J4.8(B4) U14.59(PTB11/ADC1_SE15/SPI1_SCK/UART3_)
PTB16: R24.2 U14.62(PTB16/SPI1_SOUT/UART0_RX/FTM_CL)
PTB17: R38.2 U14.63(PTB17/SPI1_SIN/UART0_TX/FTM_CLK)
PTB18: J1.1 U14.64(PTB18/CAN0_TX/FTM2_CH0/I2S0_TX_)
PTB19: J1.3 U14.65(PTB19/CAN0_RX/FTM2_CH1/I2S0_TX_)
PTB20: J4.9(A5) U14.66(PTB20/SPI2_PCS0/FB_AD31/CMP0_OU)
PTB21: R71.2 U14.67(PTB21/SPI2_SCK/FB_AD30/CMP1_OUT)
PTB22: R68.1 U14.68(PTB22/SPI2_SOUT/FB_AD29/CMP2_OU)
PTB23: J1.10 U14.69(PTB23/SPI2_SIN/SPI0_PCS5/FB_AD2)
PTC0: J1.11 U14.70(PTC0/ADC0_SE14/SPI0_PCS4/PDB0_E)
PTC1: J1.5 U14.71(PTC1/LLWU_P6/ADC0_SE15/SPI0_PCS)
PTC2: J1.14 U14.72(PTC2/ADC0_SE4B/CMP1_IN0/SPI0_PC)
PTC3: J1.16 U14.73(PTC3/LLWU_P7/CMP1_IN1/SPI0_PCS1)
PTC4: J2.4 U14.76(PTC4/LLWU_P8/SPI0_PCS0/UART1_TX)
PTC5: J1.15 U14.77(PTC5/LLWU_P9/SPI0_SCK/LPTMR0_AL)
PTC6: C56.1 R1.2 SW2.1(SW1) U8.11(INT1) U14.78(PTC6/LLWU_P10/CMP0_IN0/SPI0_SOU)
PTC7: J1.13 U14.79(PTC7/CMP0_IN1/SPI0_SIN/USB_SOF_)
PTC8: R79.2 U14.80(PTC8/ADC1_SE4B/CMP0_IN2/FTM3_CH)
PTC9: J1.9 U14.81(PTC9/ADC1_SE5B/CMP0_IN3/FTM3_CH)
PTC10: J4.12(B6) U14.82(PTC10/ADC1_SE6B/I2C1_SCL/FTM3_C)
PTC11: J4.10(B5) U14.83(PTC11/LLWU_P11/ADC1_SE7B/I2C1_S)
PTC12: J6.3(A2) U14.84(PTC12/U\A\R\T\4\_\R\T\S\/FB_AD2)
PTC13: U8.9(INT2) U14.85(PTC13/U\A\R\T\4\_\C\T\S\/FB_AD2)
PTC14: J199.3 U14.86(PTC14/UART4_RX/FB_AD25)
PTC15: J199.4 U14.87(PTC15/UART4_TX/FB_AD24)
PTC16: J1.2 U14.90(PTC16/UART3_RX/ENET0_1588_TMR0/)
PTC17: J1.4 U14.91(PTC17/UART3_TX/ENET0_1588_TMR1/)
PTC18: J6.8(B4) U14.92(PTC18/U\A\R\T\3\_\R\T\S\/ENET0_)
PTD0: J2.6 U14.93(PTD0/LLWU_P12/SPI0_PCS0/U\A\R\T)
PTD1: J2.12 U14.94(PTD1/ADC0_SE5B/SPI0_SCK/U\A\R\T)
PTD2: J2.8 U14.95(PTD2/LLWU_P13/SPI0_SOUT/UART2_R)
PTD3: J2.10 U14.96(PTD3/SPI0_SIN/UART2_TX/FTM3_CH3)
PTD4: J6.4(B2) U14.97(PTD4/LLWU_P14/SPI0_PCS1/U\A\R\T)
PTD5: J6.5(A3) U14.98(PTD5/ADC0_SE6B/SPI0_PCS2/U\A\R\)
PTD6: J6.6(B3) U14.99(PTD6/LLWU_P15/ADC0_SE7B/SPI0_PC)
PTD7: J6.7(A4) U14.100(PTD7/CMT_IRO/UART0_TX/FTM0_CH7/)
PTE0: J15.P8(DAT1) U14.1(PTE0/CLKOUT32K/ADC1_SE4A/SPI1_P)
PTE1: J15.P7(DAT0) U14.2(PTE1/LLWU_P0/ADC1_SE5A/SPI1_SOU)
PTE2: J15.P5(CLK) U14.3(PTE2/LLWU_P1/ADC0_DP2/ADC1_SE6A)
PTE3: J15.P3(CMD) U14.4(PTE3/ADC0_DM2/ADC1_SE7A/SPI1_SI)
PTE4: J15.P2(CD/DAT3) U14.5(PTE4/LLWU_P2/SPI1_PCS0/UART3_TX)
PTE5: J15.P1(DAT2) U14.6(PTE5/SPI1_PCS2/UART3_RX/SDHC0_D)
PTE6: J15.G1(SWITCH) U14.7(PTE6/SPI1_PCS3/U\A\R\T\3\_\C\T\)
PTE24: J2.20 R9.2 U8.4(SCL/SCLK) U14.31(PTE24/ADC0_SE17/UART4_TX/I2C0_S)
PTE25: J2.18 R15.2 U8.6(SDA/MOSI) U14.32(PTE25/ADC0_SE18/UART4_RX/I2C0_S)
PTE26: J2.1 R73.2 U14.33(PTE26/CLKOUT32K/ENET_1588_CLKIN)
REXT: C38.1 R58.1 U13.9(REXT)
RMII0_INT_B: J14.2 U13.18(INTRP)
RMII_RXCLK: R57.1 U14.50(PTA18/EXTAL0/FTM0_FLT2/FTM_CLKI)
RMII_XTALI: C35.1 U13.8(XI) Y2.1
RMII_XTALO: C29.1 U13.7(XO) Y2.3
RST_TGTMCU_B: D1.C(CATHODE) J3.6 J9.10(B5) J25.3 R10.2 R11.2 R45.1 U3.7(B1) U14.52(R\E\S\E\T\)
RXCLK: R57.2 U13.16(REF_CLK)
RXD0: RN1.4(PIN4) U13.13(RXD0)
RXD1: RN1.3(PIN3) U13.12(RXD1)
SDA_EXTAL: C9.1 U5.17(EXTAL0/PTA18/FTM0_FLT2/FTM_CLKI) Y1.3
SDA_JTAG_TCLK: J10.4(B2) U5.12(JTAG_TCLK/SWD_CLK/EZP_CLK/TSI0_)
SDA_JTAG_TDI: J10.8(B4) U5.13(JTAG_TDI/EZP_DI/TSI0_CH2/PTA1/U)
SDA_JTAG_TDO: J10.6(B3) U5.14(JTAG_TDO/TRACE_SWO/EZP_DO/TSI0_)
SDA_JTAG_TMS: J10.2(B1) R21.2 U5.15(JTAG_TMS/SWD_DIO/TSI0_CH4/PTA3/)
SDA_LED: D2.C(CATHODE) U5.29(PTD4/SPI0_PCS1/U\A\R\T\0\_\R\T\)
SDA_LED_R: D2.A(ANODE) R17.2
SDA_RST: J10.10(B5) R5.2 R6.1 TP5.1(PIN1) U5.19(R\E\S\E\T\)
SDA_RST_LED: D1.A(ANODE) R2.2
SDA_RST_TGTMCU_B: J5.2 U5.21(ADC0_SE9/TSI0_CH6/PTB1/I2C0_SDA)
SDA_RST_TGTMCU_J_B: J5.1 J25.1 R10.1 R14.2 U3.2(A1)
SDA_RX_EN: R16.1 R23.2 U7.5(DIR)
SDA_SPI0_CS: R3.2 TP1.1(PIN1) U5.23(ADC0_SE4B/CMP1_IN0/TSI0_CH15/PT)
SDA_SPI0_RST_B: R18.2 TP6.1(PIN1) U5.22(ADC0_SE15/TSI0_CH14/PTC1/SPI0_P)
SDA_SPI0_SCK: U2.3(A) U5.26(PTC5/SPI0_SCK/LPTMR0_ALT2/I2S0_)
SDA_SPI0_SIN: U5.28(CMP0_IN1/PTC7/SPI0_SIN/USB_SOF_) U10.5(2A)
SDA_SPI0_SOUT: U5.27(CMP0_IN0/PTC6/SPI0_SOUT/PDB0_EX) U12.3(A)
SDA_SWD_EN: R18.1 R19.1 U9.6(Y\2\)
SDA_SWD_EN_B: R25.2 U5.16(N\M\I\/E\Z\P\_\C\S\/TSI0_CH5/PT)
SDA_SWD_EN_B_R: R25.1 R26.2 U9.1(A1)
SDA_SWD_EN_R: R12.2 R13.1 R19.2 U2.5(DIR)
SDA_SWD_OE: R3.1 R33.1 U9.4(Y\1\)
SDA_SWD_OE_B: R28.2 U5.20(ADC0_SE8/TSI0_CH0/PTB0/I2C0_SCL)
SDA_SWD_OE_B_R: R27.1 R28.1 U9.3(A2)
SDA_SWD_OE_R: R33.2 R37.2 R39.1 U12.5(DIR)
SDA_USB_CONN_DN: J26.2(P2) R22.1 U4.1(A1)
SDA_USB_CONN_DP: J26.3(P3) R20.1 U6.1(A1)
SDA_USB_DN: R22.2 U5.4(USB0_DM)
SDA_USB_DP: R20.2 U5.3(USB0_DP)
SDA_USB_P5V_SENSE: R7.1 R8.2 U5.30(ADC0_SE6B/PTD5/SPI0_PCS2/U\A\R\)
SDA_USBSHIELD: J26.S1(SHLD1) J26.S2(SHLD2) J26.S3(SHLD3) J26.S4(SHLD4) L2.1
SDA_VOUT33: C11.1 J7.2 U5.5(VOUT33)
SDA_XTAL: C6.1 U5.18(XTAL0/PTA19/FTM1_FLT0/FTM_CLKIN) Y1.1
SHIELD_K64USB: J22.S1(SHLD1) J22.S2(SHLD2) J22.S3(SHLD3) J22.S4(SHLD4) L4.1
SW1_RST_B: C2.1 J25.2 SW1.2(SW2)
SWD_CLK_TGTMCU: J8.2 J9.4(B2) J11.2
SWD_CLK_TGTMCU_BUF: J8.1 U2.4(B)
SWD_DIO_TGTMCU_BUF: J12.1 U10.2(2B) U12.4(B)
TC_EXTAL_TP: TP9.1(PIN1) U5.10(EXTAL32)
TC_SDA_USB_ID_TP: J26.4(P4) TP7.1(PIN1)
TC_USB_ID_TP: J22.4(P4) R72.1 TP15.1(PIN1)
TC_XTAL_TP: TP10.1(PIN1) U5.9(XTAL32)
TP_2102_A: TP3.1(PIN1) U3.3(A2)
TP_2102_B: TP2.1(PIN1) U3.6(B2)
TRACE_SWO: J9.6(B3) R80.1
UART1_RX_TGTMCU_BUF: R24.1 U7.4(B)
UART1_RX_TGTMCU_R: U5.25(PTC4/SPI0_PCS0/UART1_TX/FTM0_CH) U7.3(A)
UART1_TX_TGTMCU_BUF: R38.1 U10.1(1B)
UART1_TX_TGTMCU_R: U5.24(CMP1_IN1/PTC3/SPI0_PCS1/UART1_R) U10.6(1A)
USB_CONN_DN: J22.2(P2) R49.1 U16.1(A1)
USB_CONN_DP: J22.3(P3) R46.1 U18.1(A1)
V_TGTMCU: C7.1 C23.1 R2.1 R11.1 SH1.1 U2.6(VCCB) U3.8(VCCB) U7.6(VCCB) U10.8(VCCB) U12.6(VCCB)
VOUT33_K64: C59.1 TP12.1(PIN1) U14.12(VOUT33)
VREFH: D4.C(CATHODE) R52.2 R53.1 R54.2 U14.23(VREFH)
VREGIN_K64: C33.1 J16.1 U14.13(VREGIN)
VTRG_EN: R29.2 R30.1 R34.2 U11.3(ENABLE)
VTRG_FAULT_B: R35.2 U5.32(PTD7/CMT_IRO/UART0_TX/FTM0_CH7/) U11.4(F\A\U\L\T\)
XTAL32_RTC: R62.1 U14.28(XTAL32)
XTAL_32.768KHZ: C44.1 R62.2 R65.2 Y3.1
XTAL_K64_MAIN: R74.1 U14.51(PTA19/XTAL0/FTM1_FLT0/FTM_CLKIN)
N20614543: C34.1 D3.3(COM_ANODE) R50.2 U13.24(R\S\T\)
N20654921: RN1.2(PIN2) U13.17(RXER)
N20657567: J13.14(L4) R36.2

Pads without a net: J2 9 15 19; J3 1 2 3 5 7 9 11 13 15; J9 7 8 9; J10 7 9; U8 15

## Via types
v1: diameter 0.508, hole 0.254, TOP to BOTTOM, 635 vias
v2: diameter 0.762, hole 0.457, TOP to BOTTOM, 9 vias

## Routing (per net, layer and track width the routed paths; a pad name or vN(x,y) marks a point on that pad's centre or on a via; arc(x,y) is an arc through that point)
GND: length 318.2
  TOP w0.127: Y1.2 27.55,42.74 ; Y1.2 28.8,42.35 ; Y1.2 26.31,42.35 ; Y1.2 27.55,41.95 ; 25.72,41.85 C9.2 24.7,41.85 ; C29.2 26.65,29.15 ; C29.2 27.16,28.65 ; C29.2 26.14,28.65 ; U8.3 56.32,42.43 56.33,42.44 v1(56.33,42.93) ; U8.12 56.82,35.5 57.14,35.19 v1(57.14,33.96) ; 9.16,17.79 J13.9 ; J13.9 9.16,20.28 ; J13.9 7.91,19.03 ; U8.5 v1(55.32,42.93) ; 47.45,12.85 C48.2 ; C48.2 47.45,13.87 ; C48.2 47.96,13.36 ; C48.2 46.94,13.36 ; C44.2 47.24,14.07 ; C44.2 46.22,14.07 ; C44.2 46.73,13.56 ; C44.2 46.73,14.58 ; 22.94,26.16 Y2.4 ; Y2.4 23.62,25.27 ; Y2.4 24.31,26.16 ; Y2.4 23.62,27.05 ; J13.12 1.21,23.91 ; J13.12 2.1,23.02 ; J13.12 1.21,22.13 ; Y2.2 25.91,28.36 ; Y2.2 25.22,29.25 ; Y2.2 24.54,28.36 ; v1(57.64,34.86) 57.64,35.3 57.32,35.62 U8.13 ; 7.91,34.58 J13.10 9.16,33.34 ; 25.72,42.83 C6.2 24.7,42.83 ; U8.16 v1(60.35,39.38) ; 26.16,25.15 C35.2
  TOP w0.178: U13.22 34.3,26.63 34.57,26.36 v1(35.04,26.36) ; v1(42.83,38.01) 42.66,37.85 41.89,37.85 41.7,38.04 U9.2
  TOP w0.203: U3.4 v1(42.63,44.86)
  TOP w0.254: v1(37.69,37.16) 37.76,37.09 U10.4 ; U5.2 17.86,41.42 v1(17.3,40.87) ; U14.24 50.03,22.51 v1(49.46,22.51) ; v1(59.81,12.35) 59.45,11.99 59.45,11.73 U14.49 ; U5.8 v1(20.41,38.88) ; U2.2 v1(47.46,44.73) ; U7.2 v1(45.23,41.15) ; U14.25 v1(49.81,20.82) ; U14.41 v1(56.6,14.54) ; U10.3 38.36,36.29 38.72,36.29 38.98,36.55 v1(38.98,36.75) ; U12.2 v1(45.01,36.12)
  TOP w0.279: U14.88 64.89,24.95
  TOP w0.305: U14.88 v1(66.55,26.61) ; 56.06,27.08 v1(57.01,26.14) ; U14.60 v1(65.45,12.75) ; U14.74 v1(70.42,17.68)
  TOP w0.381: v1(5.95,9.65) 5.55,10.05 J22.5 ; v1(36.26,32.9) 36.37,33.01 C17.2 ; R6.2 v1(26.4,45.86) ; v1(38.73,42.01) 38.87,41.87 C8.2 ; v1(47.76,42.93) C7.2 ; v1(43.8,41.13) R13.2
  TOP w0.406: v1(5.64,40.83) 5.38,40.83 5.33,40.89 J26.5
  TOP w0.508: 67.29,41.79 J6.1 ; J6.1 68.25,42.75 ; J6.1 67.29,43.7 ; J6.1 66.34,42.75 ; J15.P6 79.68,18.5 ; J15.P6 79.68,17.61 ; J15.P6 80.38,18.06 ; J15.P6 v1(78.67,18.06) ; 78.08,24.22 J15.S1 ; J15.S1 78.87,24.93 ; J15.S1 78.08,25.64 ; J15.S1 77.29,24.93 ; J199.2 73.9,35.13 ; J199.2 72.88,36.14 ; J199.2 72.88,34.11 ; C32.2 77.87,27.8 ; C32.2 76.85,27.8 ; C32.2 77.36,28.31 ; J15.S3 73.63,15.19 ; J15.S3 72.84,14.48 ; J15.S3 v1(74.7,14.48) ; 73.81,7.94 C55.2 74.32,7.43 ; 78.09,28.37 C30.2 ; C30.2 79.62,28.37 ; C30.2 78.85,29 ; C57.2 70.85,45.58 ; C57.2 71.36,45.07 ; C57.2 70.85,44.56 ; J15.S2 73.63,25.64 ; J15.S2 74.42,24.93 ; J15.S2 72.84,24.93 ; 70.1,16.85 C42.2 70.61,16.34 ; 77.59,3.58 SW3.2 76.85,2.64 ; J15.S4 v1(76.99,14.48) ; J15.S4 78.87,14.48 ; J15.S4 78.08,13.77 ; J15.S4 78.08,15.19 ; C37.2 50.2,25.69 ; C37.2 49.69,25.18 ; C37.2 50.71,25.18 ; R30.2 v1(27.48,37.24) ; 71.23,30.1 C58.2 71.74,30.61 ; 50.87,26.59 C33.2 ; 49.66,26.18 C59.2 ; 73.82,45.41 C56.2 ; C56.2 74.33,45.92 ; C56.2 73.82,46.43 ; C27.2 68.11,28.75
  TOP w0.635: C36.2 v1(18.71,25.64) ; C52.2 12.83,7.03 ; C52.2 C54.2 ; C52.2 12.83,7.79 ; C52.2 12.83,8.56 ; U1.2 v1(6.33,46.08) ; U15.2 v1(7.99,15.22) ; U6.2 v1(8.76,40.98) ; C14.2 v1(60.77,35.77) ; U11.2 32.31,35.29 v1(32.19,35.41) ; 24.39,5.72 J24.2 ; J24.2 24.39,9.56 ; J24.2 23.47,7.64 ; C41.2 23.97,19.54 v1(24.26,19.82) ; C4.2 v1(58.36,45.04) ; v1(9.85,43.21) 8.76,43.21 U4.2 ; 55.23,9.82 R70.2 v1(54.65,9.75) ; R67.2 53.84,11.75 v1(53.31,11.22) ; C12.2 17.78,37.8 v1(17.21,37.22) ; C54.2 12.83,6.24 ; C54.2 12.83,7 ; C54.2 12.19,5.48 ; C23.2 38.36,30.53 v1(38.56,30.33) ; 12.83,8.71 C50.2 12.83,9.47 ; C25.2 v1(55.86,30.44) ; R69.2 v1(53.99,10.47) ; L4.2 v1(5.84,15.58) ; SW3.2 v1(76.85,4.78) ; C38.2 v1(23.24,23.96) ; J24.3 19.3,8.64 ; J24.3 18.39,6.72 ; J24.3 17.47,8.64 ; U16.2 v1(8.6,13.2) ; R16.2 v1(48.59,41.74) ; C45.2 v1(9.94,12.48) ; 55.77,9.27 C49.2 56.28,8.76 ; C47.2 v1(67.04,14.2) ; C13.2 v1(51.82,35.86) ; C31.2 v1(18.76,27.05) ; C16.2 v1(35.69,33.58) ; C10.2 v1(14.31,40.84) ; C21.2 v1(31.67,33.49) ; 52.94,13.69 52.94,13.69 52.43,13.17 ; C18.2 v1(28.24,34.01) ; D4.A v1(45.97,19.91) ; R43.2 v1(59.73,32.17) ; C20.2 v1(17.82,31.78) ; R72.2 v1(9.77,8.83) ; 15.02,8.07 TP16.1 ; TP16.1 15.97,9.02 ; TP16.1 14.07,9.02 ; C26.2 v1(34.92,30.1) ; C15.2 v1(19.08,35.79) ; R7.2 v1(15.56,46.37) ; C34.2 v1(36.08,24.53) ; R39.2 v1(48.36,33.4) ; R58.2 v1(23.23,22.47) ; C2.2 v1(35.41,46.03) ; C39.2 v1(29.86,21.91) ; C57.2 v1(71.7,45.07) ; C24.2 v1(33.89,29.22) ; L2.2 v1(6.82,37.17) ; 51.85,13.76 C43.2 v1(52.47,14.89) ; C5.2 v1(61.02,42.53) ; C51.2 v1(35.73,9.21) ; C11.2 v1(13.27,39.49) ; SW2.2 v1(76.85,50.95) ; R31.2 v1(48.27,36.57) ; C22.2 v1(34.64,31.08) ; SW1.1 v1(3.97,48.66) ; 61.55,8.34 R74.2 ; C53.2 v1(3.35,4.97) ; 39.57,8.18 C40.2 38.94,7.42 ; C3.2 v1(53.7,45.02) ; C1.2 v1(11.23,44.34) ; U18.2 v1(8.6,10.01) ; C28.2 v1(38.49,28.34)
  TOP w1.016: U17.1 v1(31.91,12.87)
  GND w0.127: J3.12 40.6,3.76 ; J3.12 40.6,1.4 ; J3.12 41.78,2.58 ; J3.12 39.42,2.58 ; J2.14 26.49,51.85 ; J2.14 27.52,50.83 ; J2.14 26.49,49.8 ; J2.14 25.46,50.83 ; 7.91,34.58 J13.10 ; J13.10 10.4,34.58 ; J13.10 9.16,35.83 ; J13.10 9.16,33.34 ; J3.14 43.14,3.76 ; J3.14 43.14,1.4 ; J3.14 44.32,2.58 ; J3.14 41.96,2.58 ; TP16.1 15.02,9.97 ; TP16.1 14.07,9.02 ; TP16.1 15.02,8.07 ; TP16.1 15.97,9.02 ; 23.47,7.64 J24.2 ; J24.2 24.39,9.56 ; J24.2 24.39,5.72 ; J24.2 25.3,7.64 ; J6.1 67.29,43.7 ; J6.1 66.34,42.75 ; J6.1 68.25,42.75 ; J6.1 67.29,41.79 ; J10.3 27.02,32.57 ; 71.86,35.13 J199.2 ; J199.2 72.88,34.11 ; J199.2 72.88,36.14 ; J199.2 73.9,35.13 ; J13.12 2.1,23.02 ; J13.12 1.21,22.13 ; J13.12 1.21,23.91 ; 7.03,1.98 J27.2 ; J27.2 6.08,2.93 ; J27.2 7.99,2.93 ; J27.2 7.03,3.88 ; J2.3 39.19,49.31 ; J2.3 40.22,48.29 ; J2.3 38.16,48.29 ; J2.3 39.19,47.26 ; 7.91,19.03 J13.9 ; J13.9 9.16,20.28 ; J13.9 10.4,19.03 ; J13.9 9.16,17.79 ; J24.3 19.3,8.64 ; J24.3 17.47,8.64 ; J24.3 18.39,6.72 ; J24.3 18.39,10.56 ; J9.3 42.63,32.57 ; J10.5 27.02,33.84 ; J9.5 42.63,33.84
  INT_1 w0.127: J13.12 2.1,23.02 ; J13.12 1.21,22.13 ; J13.12 1.21,23.91 ; J27.2 7.03,3.88 ; J27.2 7.03,1.98 ; J27.2 7.99,2.93 ; J27.2 6.08,2.93 ; 7.91,19.03 J13.9 ; 7.91,34.58 J13.10
  INT_1 w0.508: J3.14 44.04,3.48 ; J3.14 43.14,1.4 ; J3.14 42.24,3.48 ; J3.14 42.24,1.68 ; 19.3,10.56 J24.3 19.3,8.64 ; 39.7,3.48 J3.12 ; J3.12 40.6,1.4 ; J3.12 39.7,1.68 ; J3.12 41.5,3.48 ; 23.47,7.64 J24.2 ; J24.2 25.3,9.56 ; J24.2 25.3,7.64 ; J24.2 24.39,9.56
  BOTTOM w0.381: J199.2 72.88,36.14 ; J199.2 73.9,35.13 ; J199.2 73.66,35.91 ; J2.3 39.19,49.31 ; J2.3 39.98,49.08 ; J2.3 38.16,48.29 ; J2.3 40.22,48.29 ; J2.3 38.4,47.49 ; 14.07,9.02 TP16.1 ; TP16.1 15.02,9.97 ; TP16.1 15.97,9.02 ; TP16.1 14.28,8.28 ; TP16.1 15.02,8.07 ; J27.2 7.03,3.88 ; J27.2 6.3,2.19 ; J27.2 7.99,2.93 ; J27.2 7.03,1.98 ; J27.2 6.08,2.93 ; 7.91,19.03 J13.9 ; J13.9 8.21,18.09 ; J13.9 9.16,17.79 ; J13.9 10.4,19.03 ; J13.9 9.16,20.28 ; 25.46,50.83 J2.14 ; J2.14 25.7,50.03 ; J2.14 27.52,50.83 ; J2.14 26.49,49.8 ; J2.14 26.49,51.85 ; 7.91,34.58 J13.10 ; J13.10 8.21,33.64 ; J13.10 9.16,35.83 ; J13.10 9.16,33.34 ; J13.10 10.4,34.58 ; 42.63,32.57 J9.3 42.5,33.11 ; J24.3 19.3,6.72 ; J24.3 17.47,6.72 ; J24.3 18.39,6.72 ; 0.51,22.33 J13.12 ; J13.12 1.21,23.91 ; J13.12 1.21,22.13 ; J13.12 1.9,23.71 ; J13.12 2.1,23.02 ; J9.5 42.5,33.3
  vias: v1(1.01,18.42) v1(1.03,4.8) v1(1.32,35.24) v1(1.69,3.26) v1(1.86,50.19) v1(2.79,32.22) v1(3.11,51.38) v1(3.12,18.4) v1(3.14,1.75) v1(4.15,35.31) v1(4.58,52.21) v1(4.6,0.97) v1(6.48,52.45) v1(6.66,0.69) v1(6.96,35.3) v1(7.07,18.35) v1(8.32,31.3) v1(8.52,52.46) v1(8.54,22.28) v1(8.79,0.69) v1(9.83,41.7) v1(9.81,11.03) v1(10.14,48.28) v1(10.75,52.45) v1(11.02,0.69) v1(11.33,2.21) v1(11.66,4.34) v1(11.94,36.15) v1(12.36,27.46) v1(13.16,7.79) v1(13.26,16.81) v1(13.31,24.59) v1(13.3,9.34) v1(13.72,31.34) v1(14.97,16.84) v1(15.03,20.98) v1(15.17,26.2) v1(15.36,37.91) v1(16.3,47.14) v1(16.29,29.9) v1(16.31,42.39) v1(17.29,47.3) v1(17.76,34.43) v1(18.21,0.8) v1(18.45,21.46) v1(19.04,2.11) v1(19.16,6.41) v1(19.62,42.25) v1(19.71,0.85) v1(20.06,5.32) v1(20.16,52.3) v1(20.12,47.81) v1(20.45,43.06) v1(20.43,41.46) v1(21.26,42.24) v1(21.8,34.08) v1(21.71,31.47) v1(22.25,30.34) v1(22.24,24.53) v1(22.67,52.21) v1(22.69,26.99) v1(22.72,21.55) v1(22.88,37.03) v1(23.5,0.84) v1(23.62,10.19) v1(24.36,42.34) v1(25.21,52.28) v1(25.21,47.67) v1(25.54,37.5) v1(25.89,25) v1(25.95,7.76) v1(26.69,12.36) v1(26.67,11.28) v1(27.39,33.28) v1(27.48,35.64) v1(27.47,28.99) v1(27.43,27.14) v1(27.59,47.61) v1(27.73,52.21) v1(27.73,50.09) v1(27.97,12.4) v1(28.05,11.33) v1(29.1,42.31) v1(29.42,44.69) v1(30.35,50.22) v1(30.31,48.92) v1(30.56,26.38) v1(31.66,42.44) v1(31.63,27.41) v1(31.63,25.6) v1(32.67,26.38) v1(32.84,50.22) v1(32.82,22.12) v1(33.07,45.13) v1(33.33,14.91) v1(34.01,20.05) v1(35.22,40.21) v1(35.37,50.22) v1(35.41,49.01) v1(36.16,22.98) v1(36.22,45.37) v1(37.87,44.75) v1(37.92,50.18) v1(39.26,22.14) v1(39.43,24.42) v1(39.81,8.63) v1(40.51,49.72) v1(40.56,21.33) v1(41.76,24.22) v1(41.77,10.65) v1(42.48,27.84) v1(42.71,22.07) v1(43.12,31.93) v1(44.27,10.92) v1(44.36,44.38) v1(44.84,40.35) v1(44.83,16.45) v1(44.92,21.35) v1(45.14,32.63) v1(45.14,29.41) v1(45.38,12.05) v1(46,31.92) v1(46.96,51.71) v1(47.4,49.52) v1(48.12,18.4) v1(48.28,28.02) v1(49.16,32.69) v1(49.42,3.77) v1(49.9,0.98) v1(50.07,16.76) v1(50.02,7.01) v1(50.66,26.3) v1(50.71,46.74) v1(50.88,29.25) v1(51.11,32.74) v1(51.41,44.38) v1(51.61,49.49) v1(52.19,0.88) v1(52.99,32.72) v1(53.35,19.95) v1(53.5,22.35) v1(54.15,49.54) v1(54.61,0.88) v1(55.06,20.1) v1(55.66,21.43) v1(55.66,18.52) v1(56.5,25.27) v1(56.82,8.59) v1(56.94,24.5) v1(57.18,51.53) v1(57.16,4.41) v1(57.37,0.9) v1(58.07,23.46) v1(58.62,15.17) v1(58.85,22.61) v1(59.16,26.63) v1(59.48,13.19) v1(59.56,27.56) v1(59.54,8.7) v1(59.73,51.52) v1(59.75,4.37) v1(60.72,9.9) v1(60.89,19.29) v1(60.93,46.1) v1(60.92,20.7) v1(61.07,40.03) v1(61.38,7.66) v1(62.1,18.98) v1(62.23,51.55) v1(62.31,0.85) v1(62.49,36.46) v1(62.46,24.36) v1(62.48,21.77) v1(62.5,42.65) v1(62.51,38.42) v1(62.5,34.35) v1(62.52,33.19) v1(63.48,23.45) v1(63.54,20.09) v1(63.6,46.15) v1(64.25,6.85) v1(64.98,24.36) v1(64.95,21.49) v1(65.01,28.79) v1(65.07,1.23) v1(65.26,41.6) v1(65.3,38.77) v1(65.78,44.99) v1(66.26,32.79) v1(66.34,11.15) v1(66.4,17.87) v1(66.55,45.56) v1(66.64,22.85) v1(66.74,21.86) v1(66.85,11.99) v1(67.18,31.22) v1(67.93,21.42) v1(68.26,28.25) v1(68.31,19.42) v1(68.46,46.32) v1(69.17,33.68) v1(69.17,32.4) v1(69.14,26.59) v1(69.17,12.54) v1(69.23,29.07) v1(69.26,14.42) v1(69.78,46.37) v1(70.26,19.74) v1(70.47,9.52) v1(70.63,12.65) v1(70.86,20.67) v1(71.15,26.96) v1(71.63,16.44) v1(71.62,5.07) v1(71.85,52.56) v1(71.85,10.97) v1(72,48.2) v1(72.04,7.87) v1(72.17,23.54) v1(72.21,24.92) v1(72.37,9.5) v1(72.38,0.9) v1(72.55,42.68) v1(72.51,30.87) v1(73.48,22.96) v1(73.48,20.92) v1(73.55,41.56) v1(73.57,38.9) v1(73.54,19.26) v1(73.64,36.41) v1(73.76,47.1) v1(73.71,12.87) v1(73.85,45.12) v1(73.88,43.94) v1(74.27,52.56) v1(74.23,21.91) v1(74.76,7.46) v1(74.87,0.9) v1(74.98,22.96) v1(74.98,20.94) v1(75.21,26.31) v1(75.27,16.02) v1(75.4,47.91) v1(75.46,15.1) v1(75.6,10.9) v1(75.76,22.31) v1(76.14,24.58) v1(76.39,52.36) v1(76.33,17.93) v1(76.61,23) v1(76.81,16.34) v1(76.96,1.32) v1(77.28,22.29) v1(77.4,48.03) v1(77.79,19.29) v1(77.74,17.67) v1(77.81,20.4) v1(78.24,51.37) v1(78.21,23.01) v1(78.49,16.43) v1(78.68,2.42) v1(79.3,24.94) v1(79.66,49.8) v1(79.91,3.81) v1(80.37,47.96) v1(80.5,43.65) v1(80.49,30.28) v1(80.45,27.69) v1(80.59,41.84) v1(80.56,39.04) v1(80.54,32.26) v1(80.51,9.33) v1(80.68,36.22) v1(80.61,34.07)
P3V3: length 96.8
  TOP w0.127: U8.1 v1(57.32,42.93) ; U8.14 v1(60.35,38.38)
  TOP w0.254: v1(60.35,38.38) 60.77,37.96 C14.1
  TOP w0.381: v1(57.32,42.93) 57.67,43.28 C4.1
  TOP w0.508: 26.55,17.68 J18.2 ; J18.2 28.46,17.68 ; J18.2 27.51,18.64 ; J18.2 27.51,16.73 ; L3.1 28.99,31.89 29.27,32.17 R42.1 ; J15.P4 v1(78.64,20.61) ; 36.83,9.95 D11.C ; D11.C 36.83,11.73 ; D11.C 38.13,10.84 ; J19.1 34.95,17.41 ; J19.1 35.91,16.46 ; J19.1 34,16.46 ; 40.22,15.41 R66.1 40.98,16.04 ; J20.1 38.47,17.38 ; J20.1 38.47,15.48 ; J20.1 37.51,16.43 ; J20.1 39.42,16.43 ; R64.1 42.42,15.79 ; 29.92,17.7 J17.2 ; J17.2 30.88,18.65 ; J17.2 31.83,17.7 ; J17.2 30.88,16.75 ; 25.16,18.44 R61.1 25.67,18.95 ; 33.3,18.93 R60.1 ; 36.78,8.18 C40.1 37.41,8.94
  TOP w0.635: C57.1 69.83,43.95 69.83,43.95 J6.2 ; R1.1 v1(71.79,46.1) ; v1(59.77,33.3) 59.61,33.14 R40.1 ; R32.1 v1(51.04,36.57) ; R9.1 v1(52.09,43.77) ; D12.2 v1(75.63,11.77) ; R75.1 v1(74.68,6.48) ; C4.1 59.23,43.28 C5.1 v1(59.49,44.7) ; SH1.2 v1(37.01,29.93) ; R15.1 v1(51.02,43.08) ; L3.1 v1(28.99,30.13) ; C58.1 71.23,31.95 71.87,32.59 J199.1 ; C30.1 v1(78.85,25.97) ; C32.1 v1(77.36,26)
  BOTTOM w0.508: 30.88,16.75 J17.2 ; J17.2 29.92,17.7 ; J17.2 31.83,17.7 ; J17.2 30.14,16.96 ; J17.2 31.61,16.96 ; J17.2 30.88,18.65 ; J17.2 31.61,18.44 ; J17.2 30.14,18.44 ; 29.54,3.48 J3.4 ; J3.4 31.34,1.68 ; J3.4 29.54,1.68 ; J3.4 31.34,3.48 ; J20.1 38.47,17.38 ; J20.1 37.51,17.38 ; J20.1 39.42,16.43 ; J20.1 37.51,15.48 ; J20.1 37.51,16.43 ; J20.1 39.42,17.38 ; 69.09,43.48 J6.2 ; J6.2 69.83,43.7 ; J6.2 69.83,41.79 ; J6.2 70.79,42.75 ; J6.2 69.09,42.01 ; J6.2 68.88,42.75 ; J6.2 70.57,43.48 ; 35.91,16.46 J19.1 34,16.46 ; J3.8 36.42,3.48 ; J3.8 34.62,3.48 ; J3.8 34.62,1.68 ; J3.8 36.42,1.68 ; 71.86,31.57 J199.1 ; J199.1 72.88,31.57 ; J199.1 71.86,33.6 ; J199.1 73.9,32.59 ; J199.1 73.9,31.57 ; J199.1 72.88,33.6 ; J199.1 71.86,32.59 ; J18.2 28.24,18.42 ; J18.2 26.55,17.68 ; J18.2 26.77,16.95 ; J18.2 27.51,18.64 ; J18.2 26.77,18.42
  vias: v1(26.24,17.47) v1(27.5,18.91) v1(32.26,17.77) v1(33.04,18.63) v1(33.54,16.24) v1(36.5,12.06) v1(36.73,9.28) v1(37.95,9.26) v1(39.73,16.01) v1(41.79,15.99)
